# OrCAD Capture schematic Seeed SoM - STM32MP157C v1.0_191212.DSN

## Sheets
1 02 MPU_1: size A3; rev: v1.01
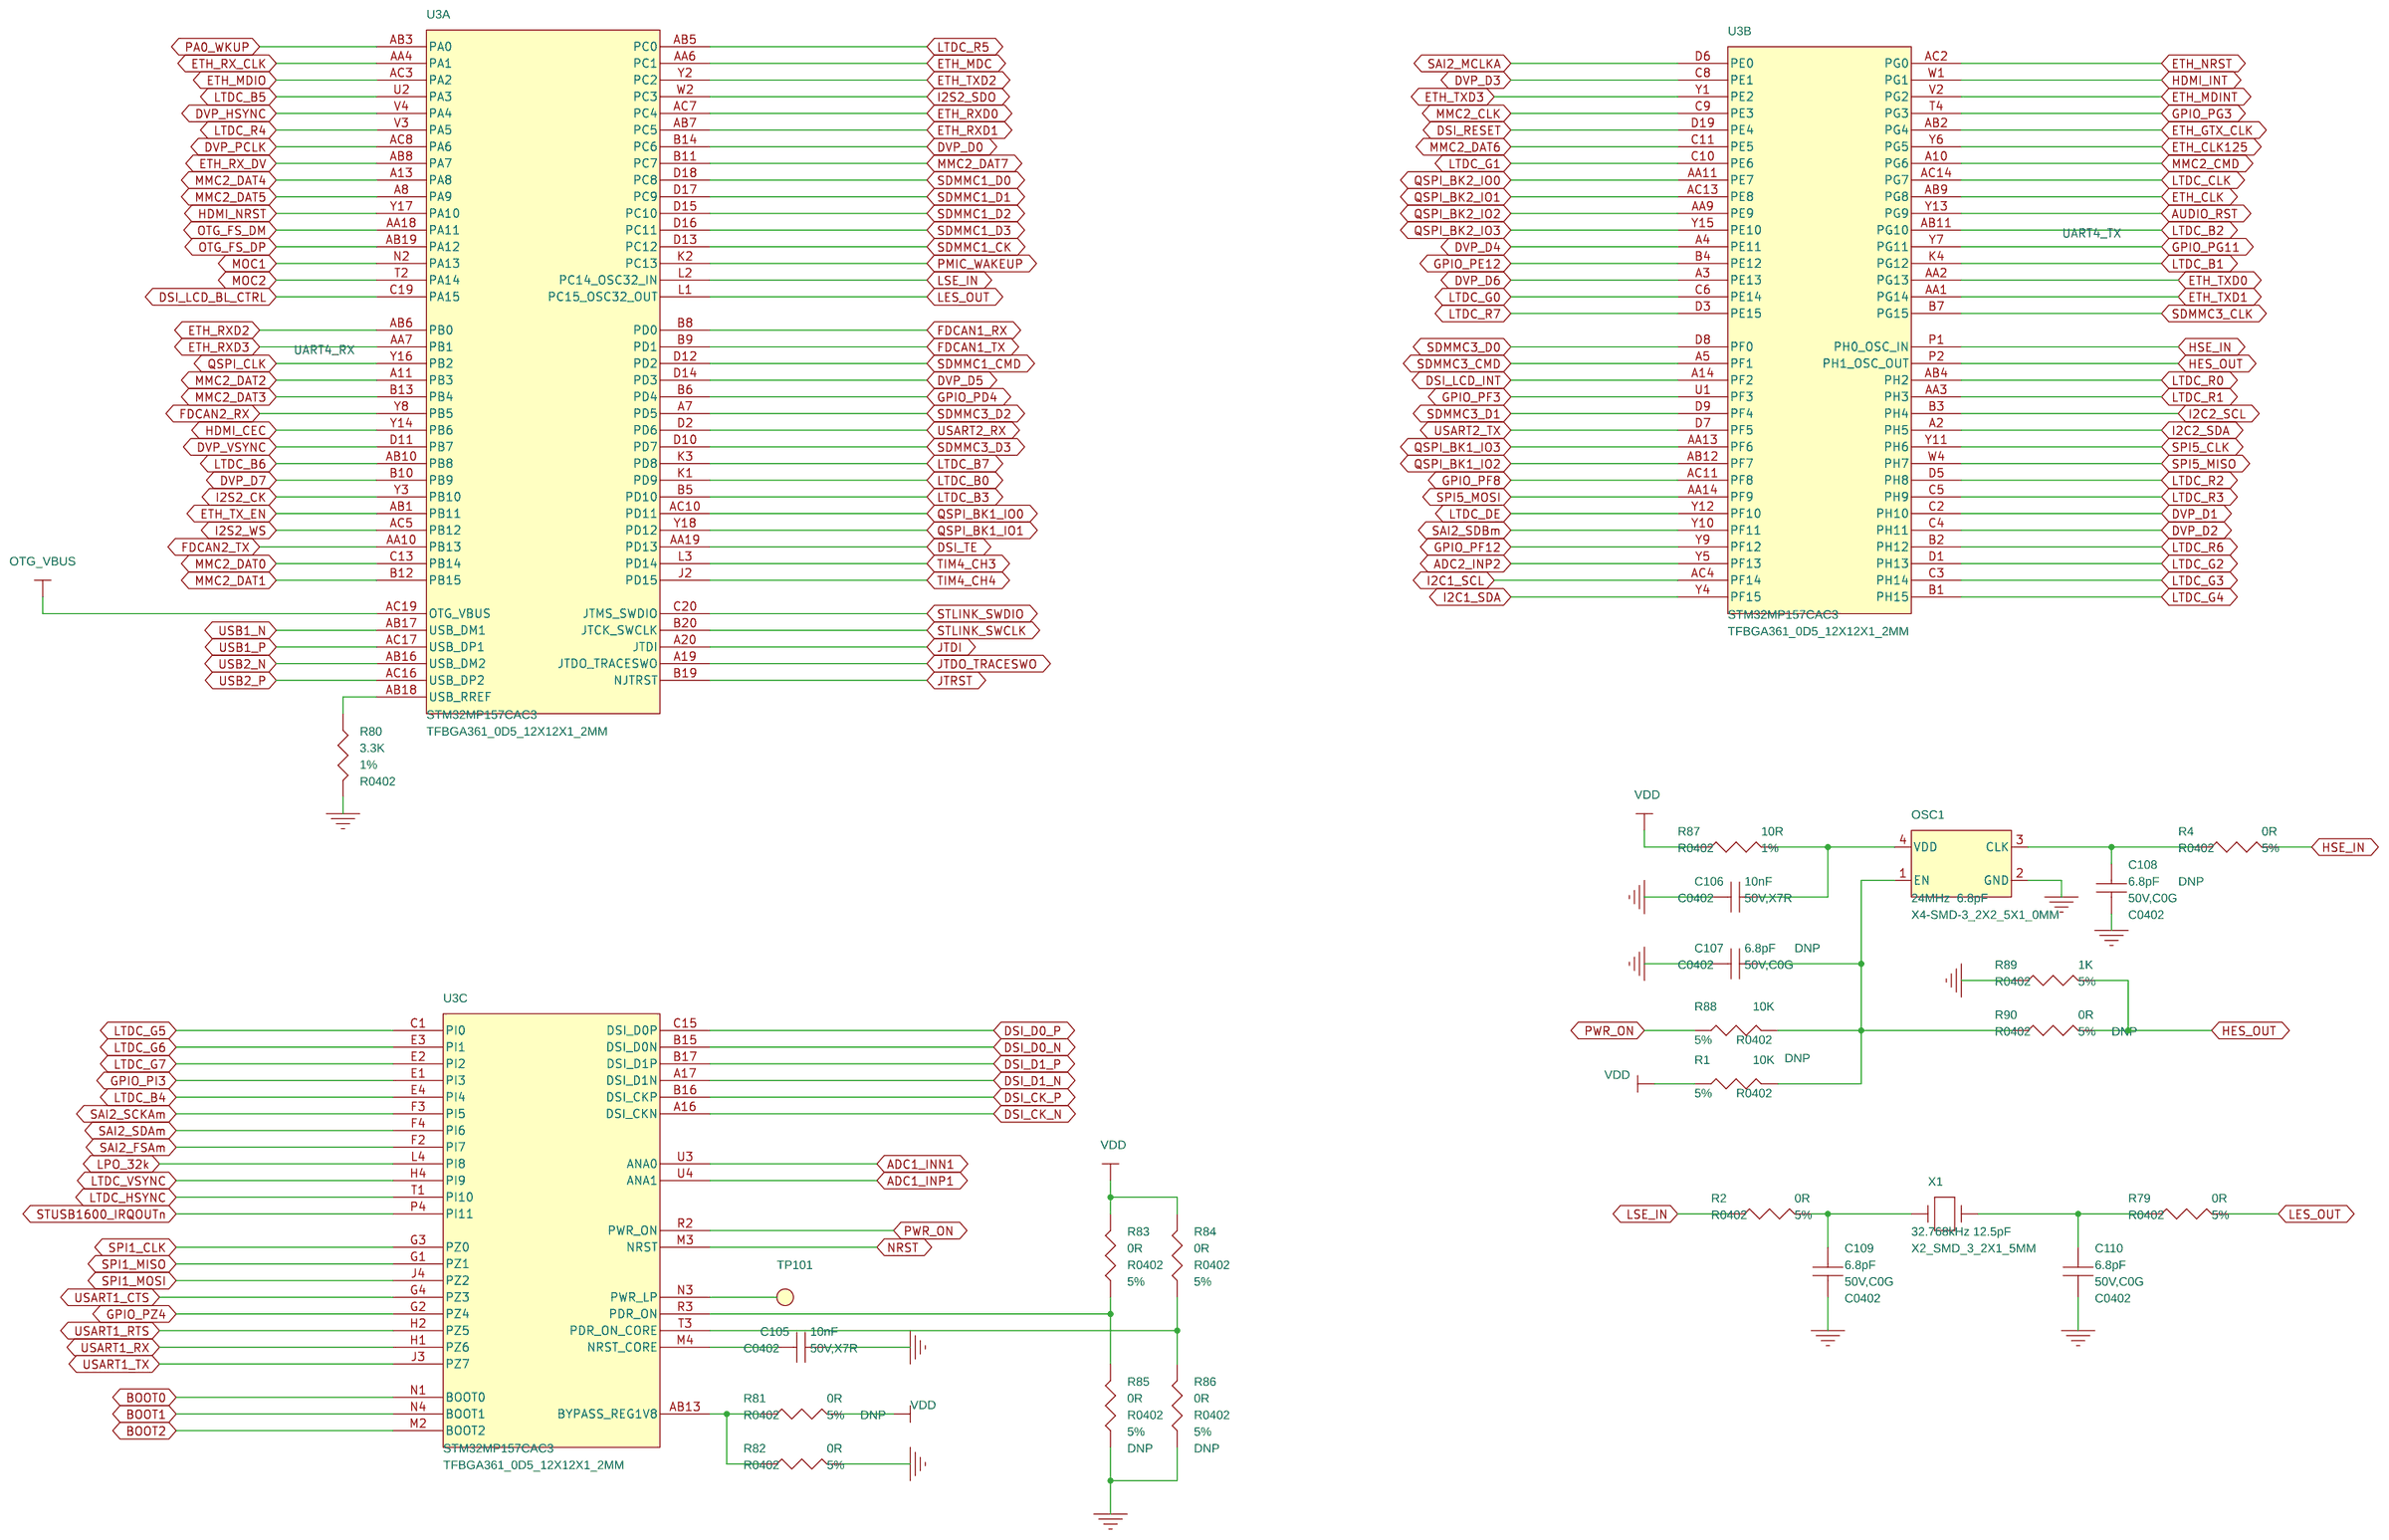
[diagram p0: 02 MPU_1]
2 03 MPU_2: size A3
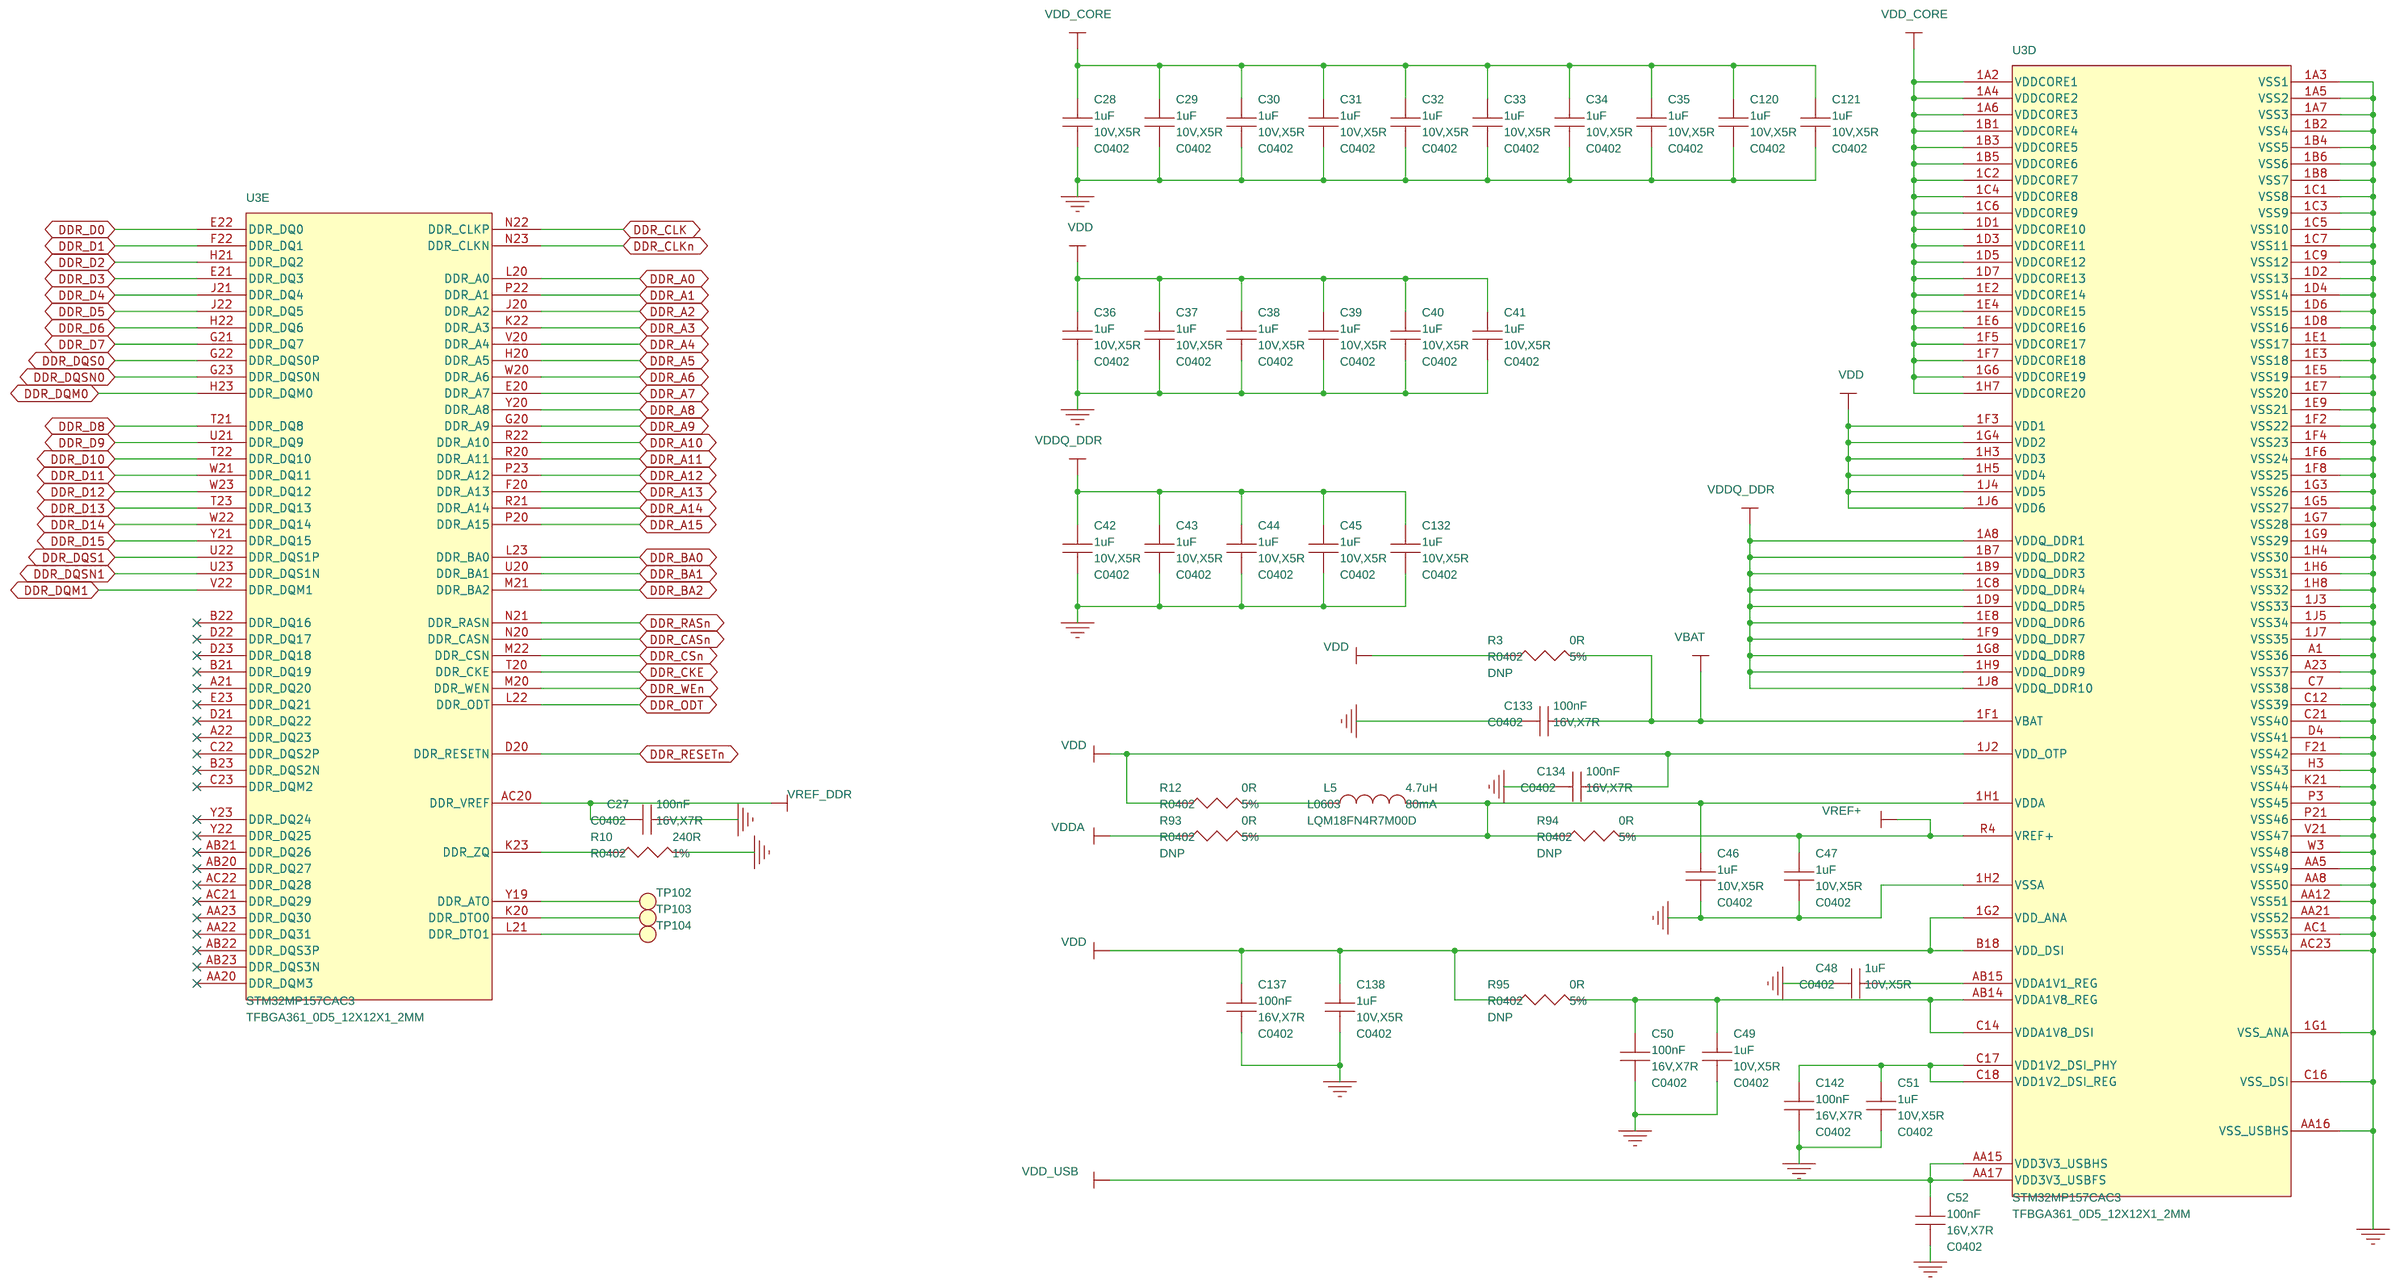
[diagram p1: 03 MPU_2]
3 04 DDR3: size A3
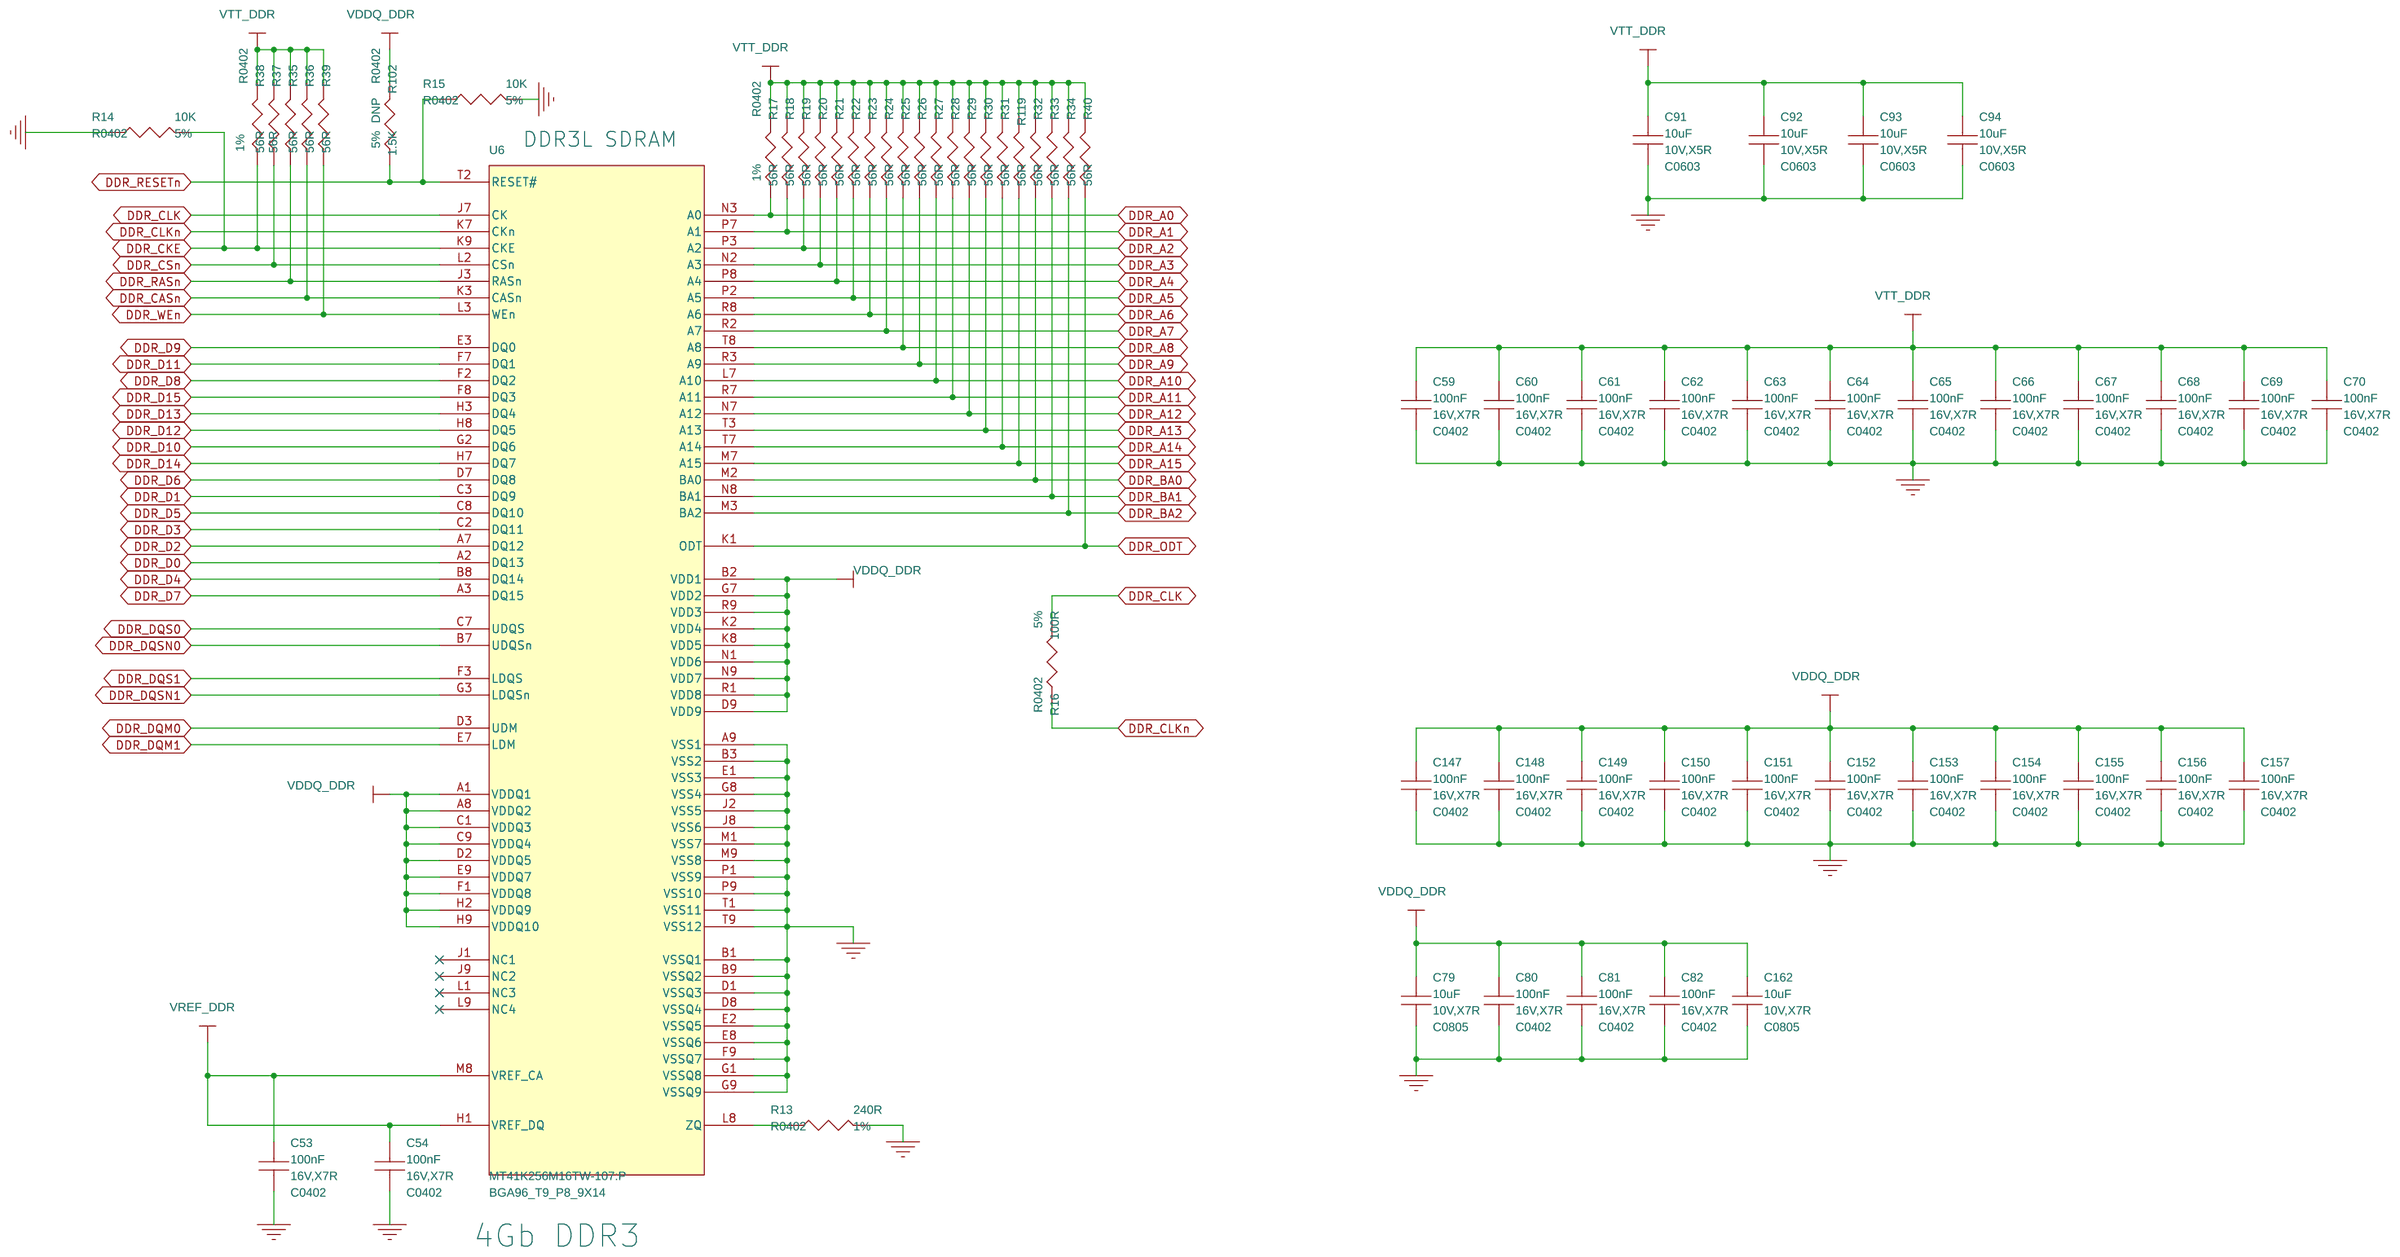
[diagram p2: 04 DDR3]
4 05 eMMC: size A3
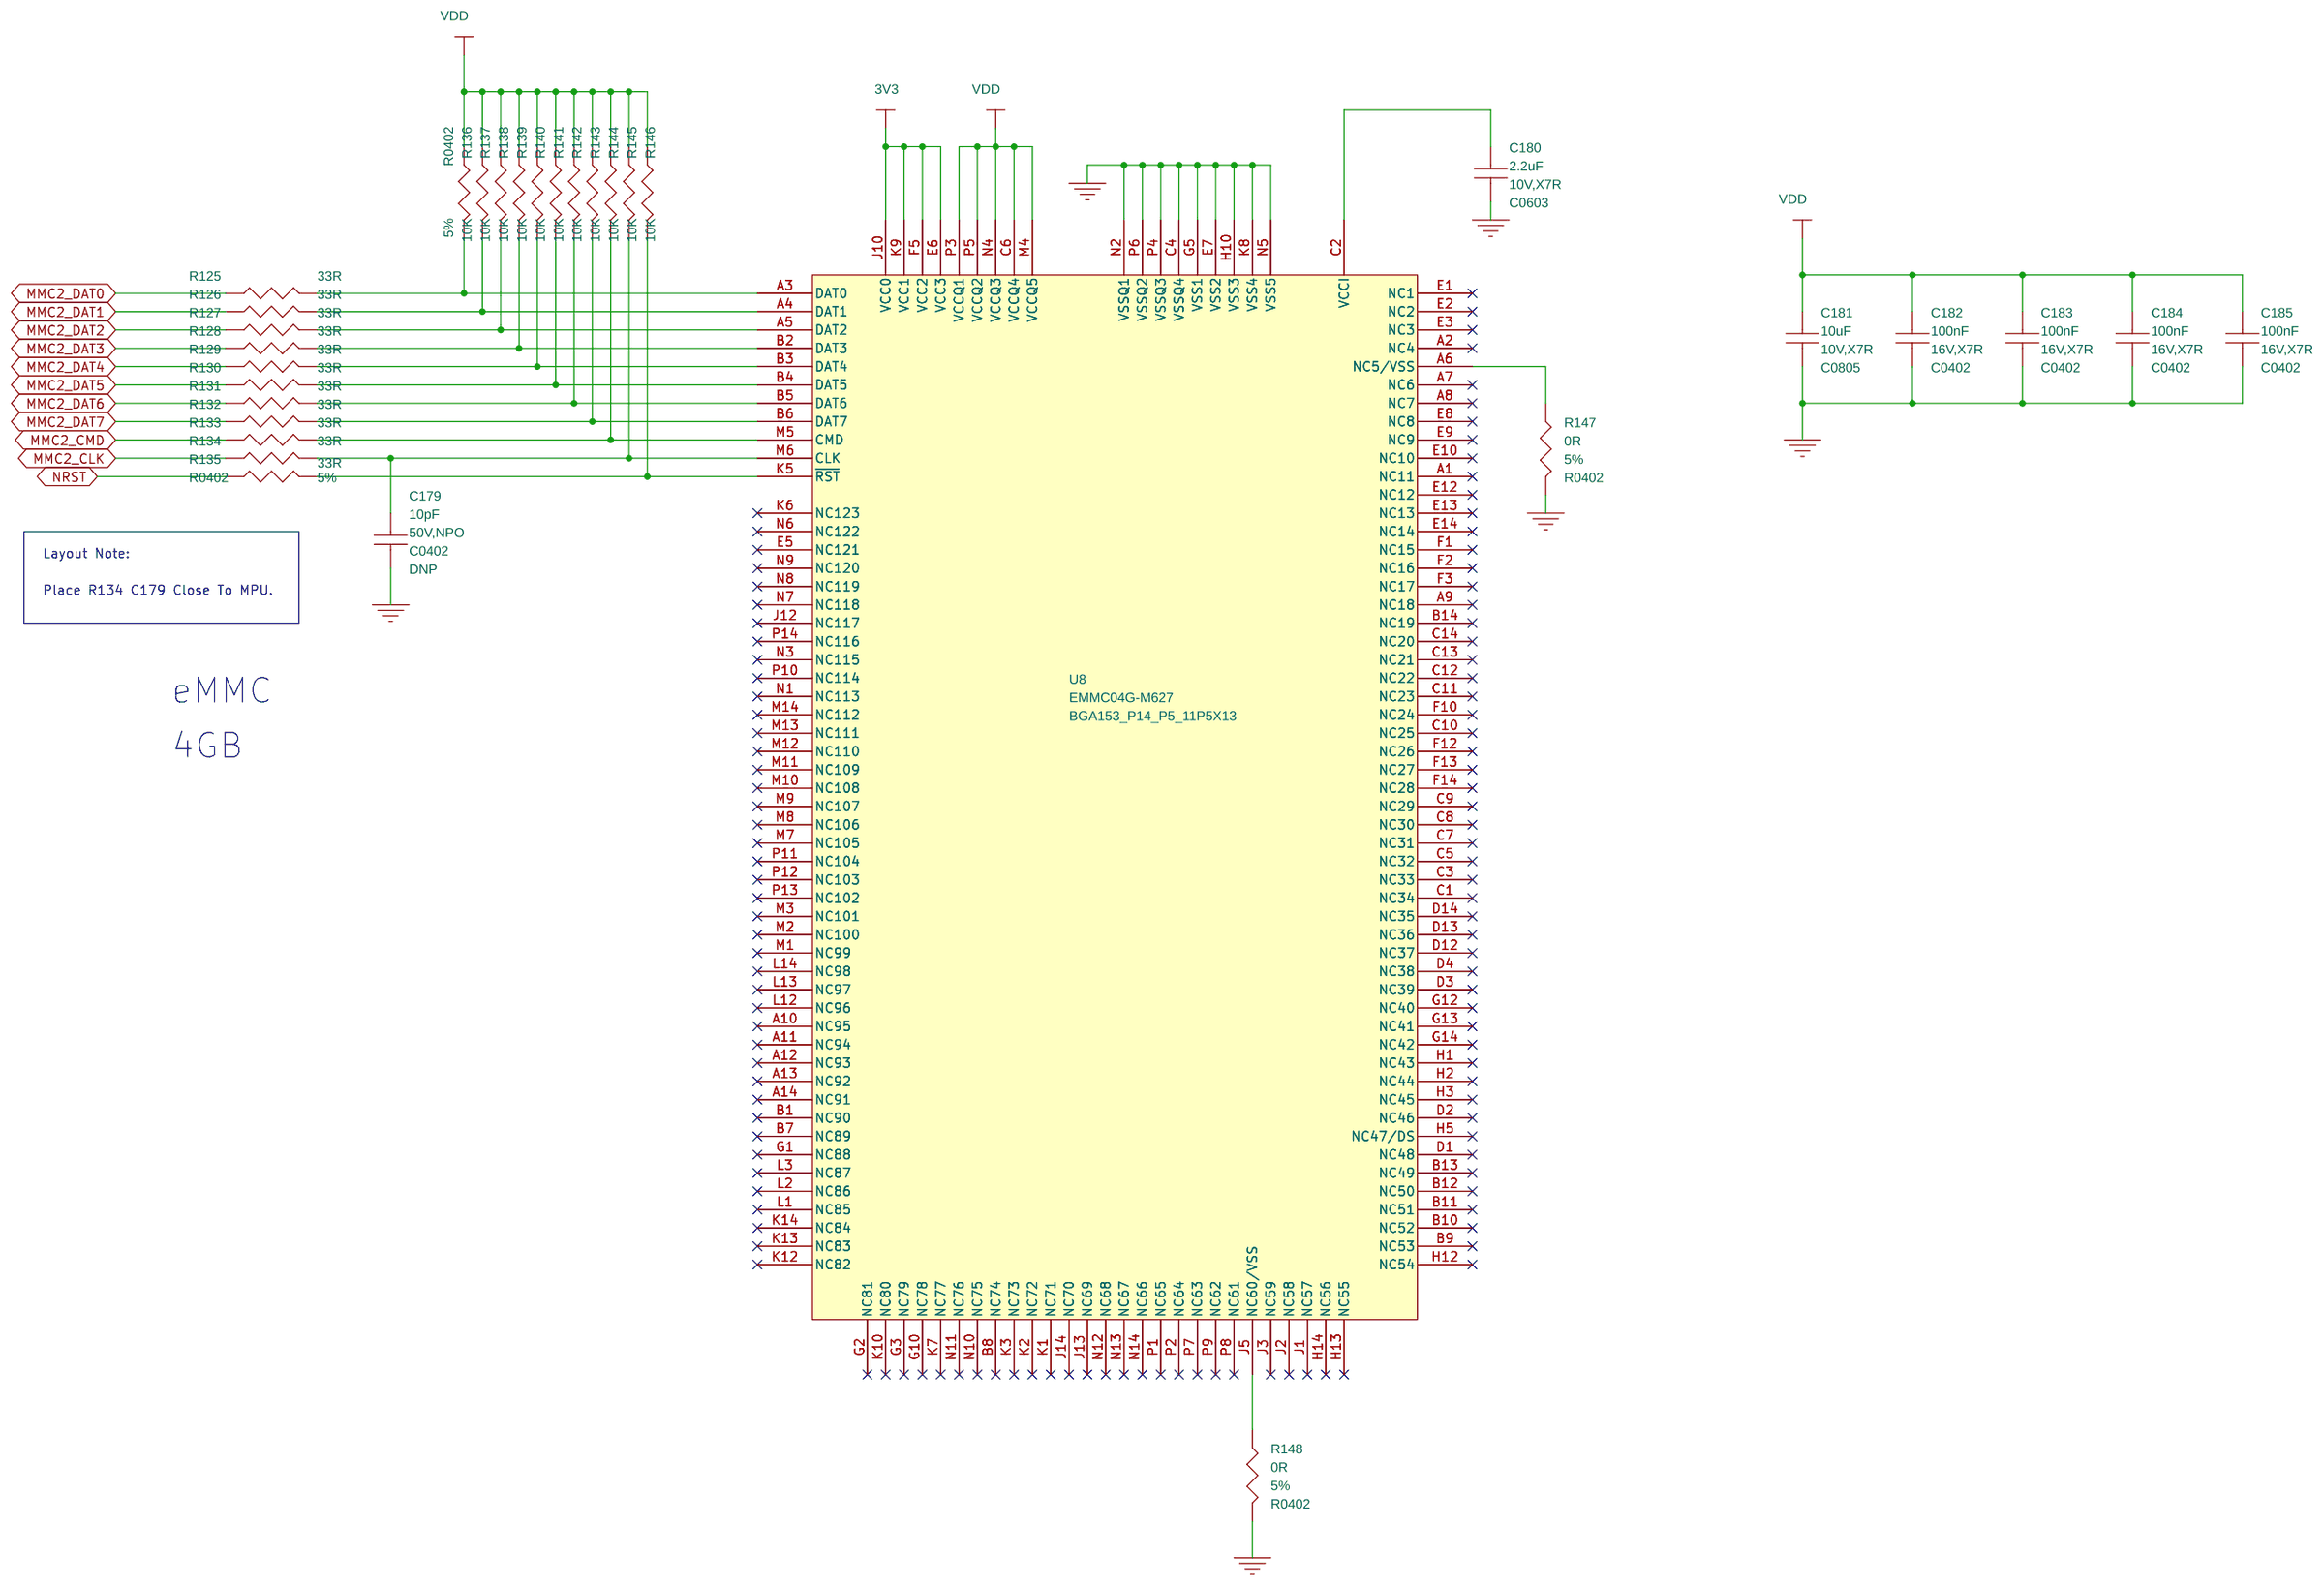
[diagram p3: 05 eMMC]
5 06 PMU: size A3
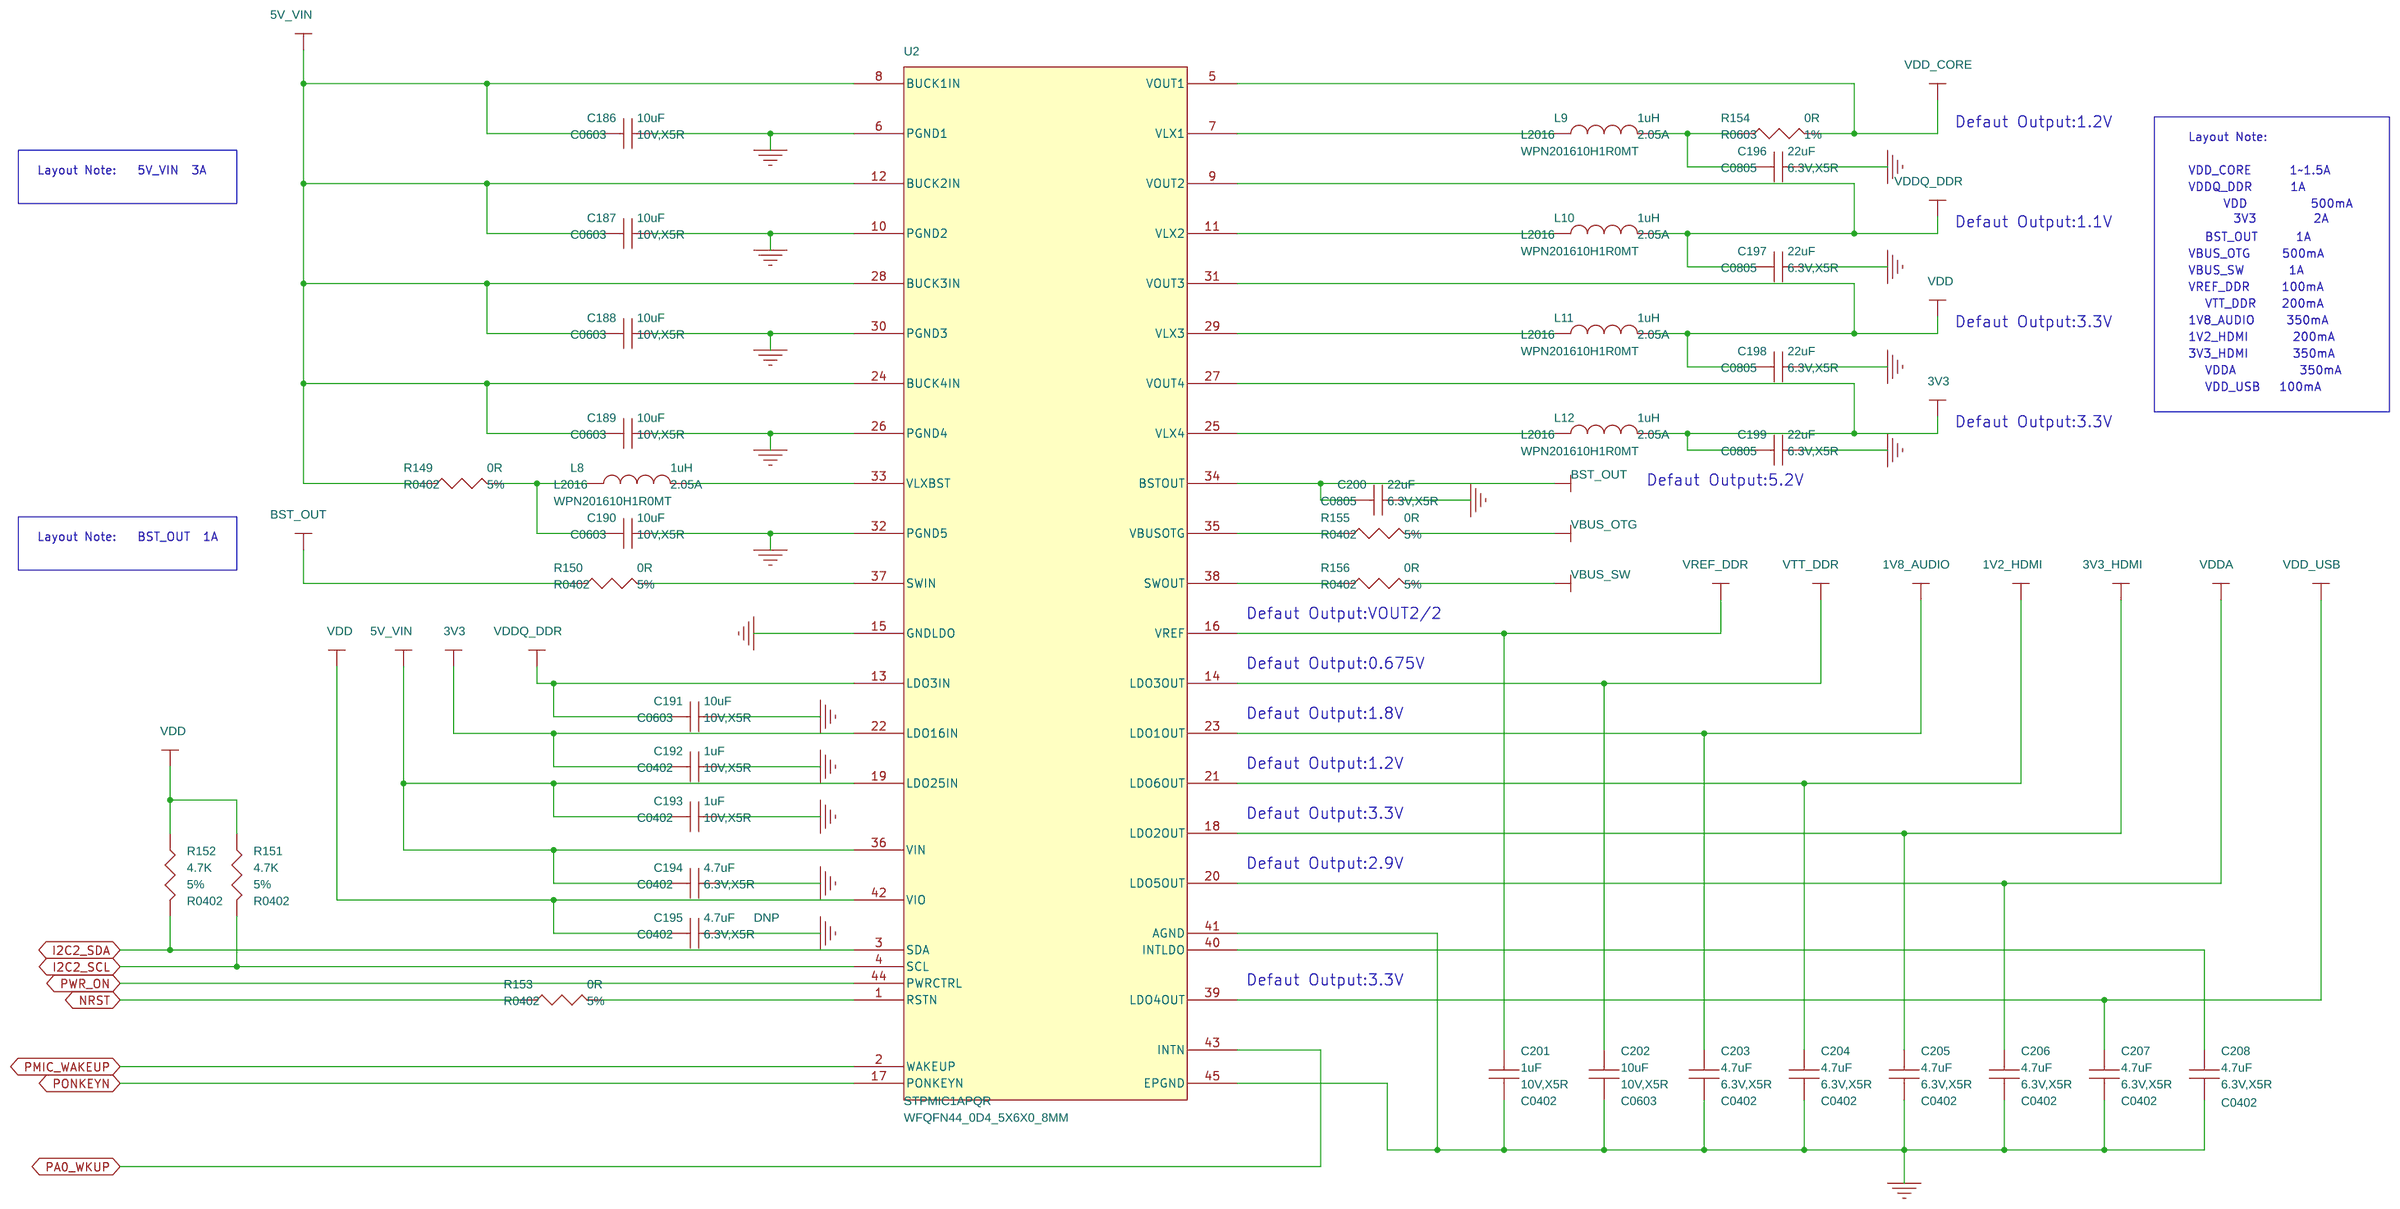
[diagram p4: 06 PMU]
6 07 PINOUT/LED: size A3
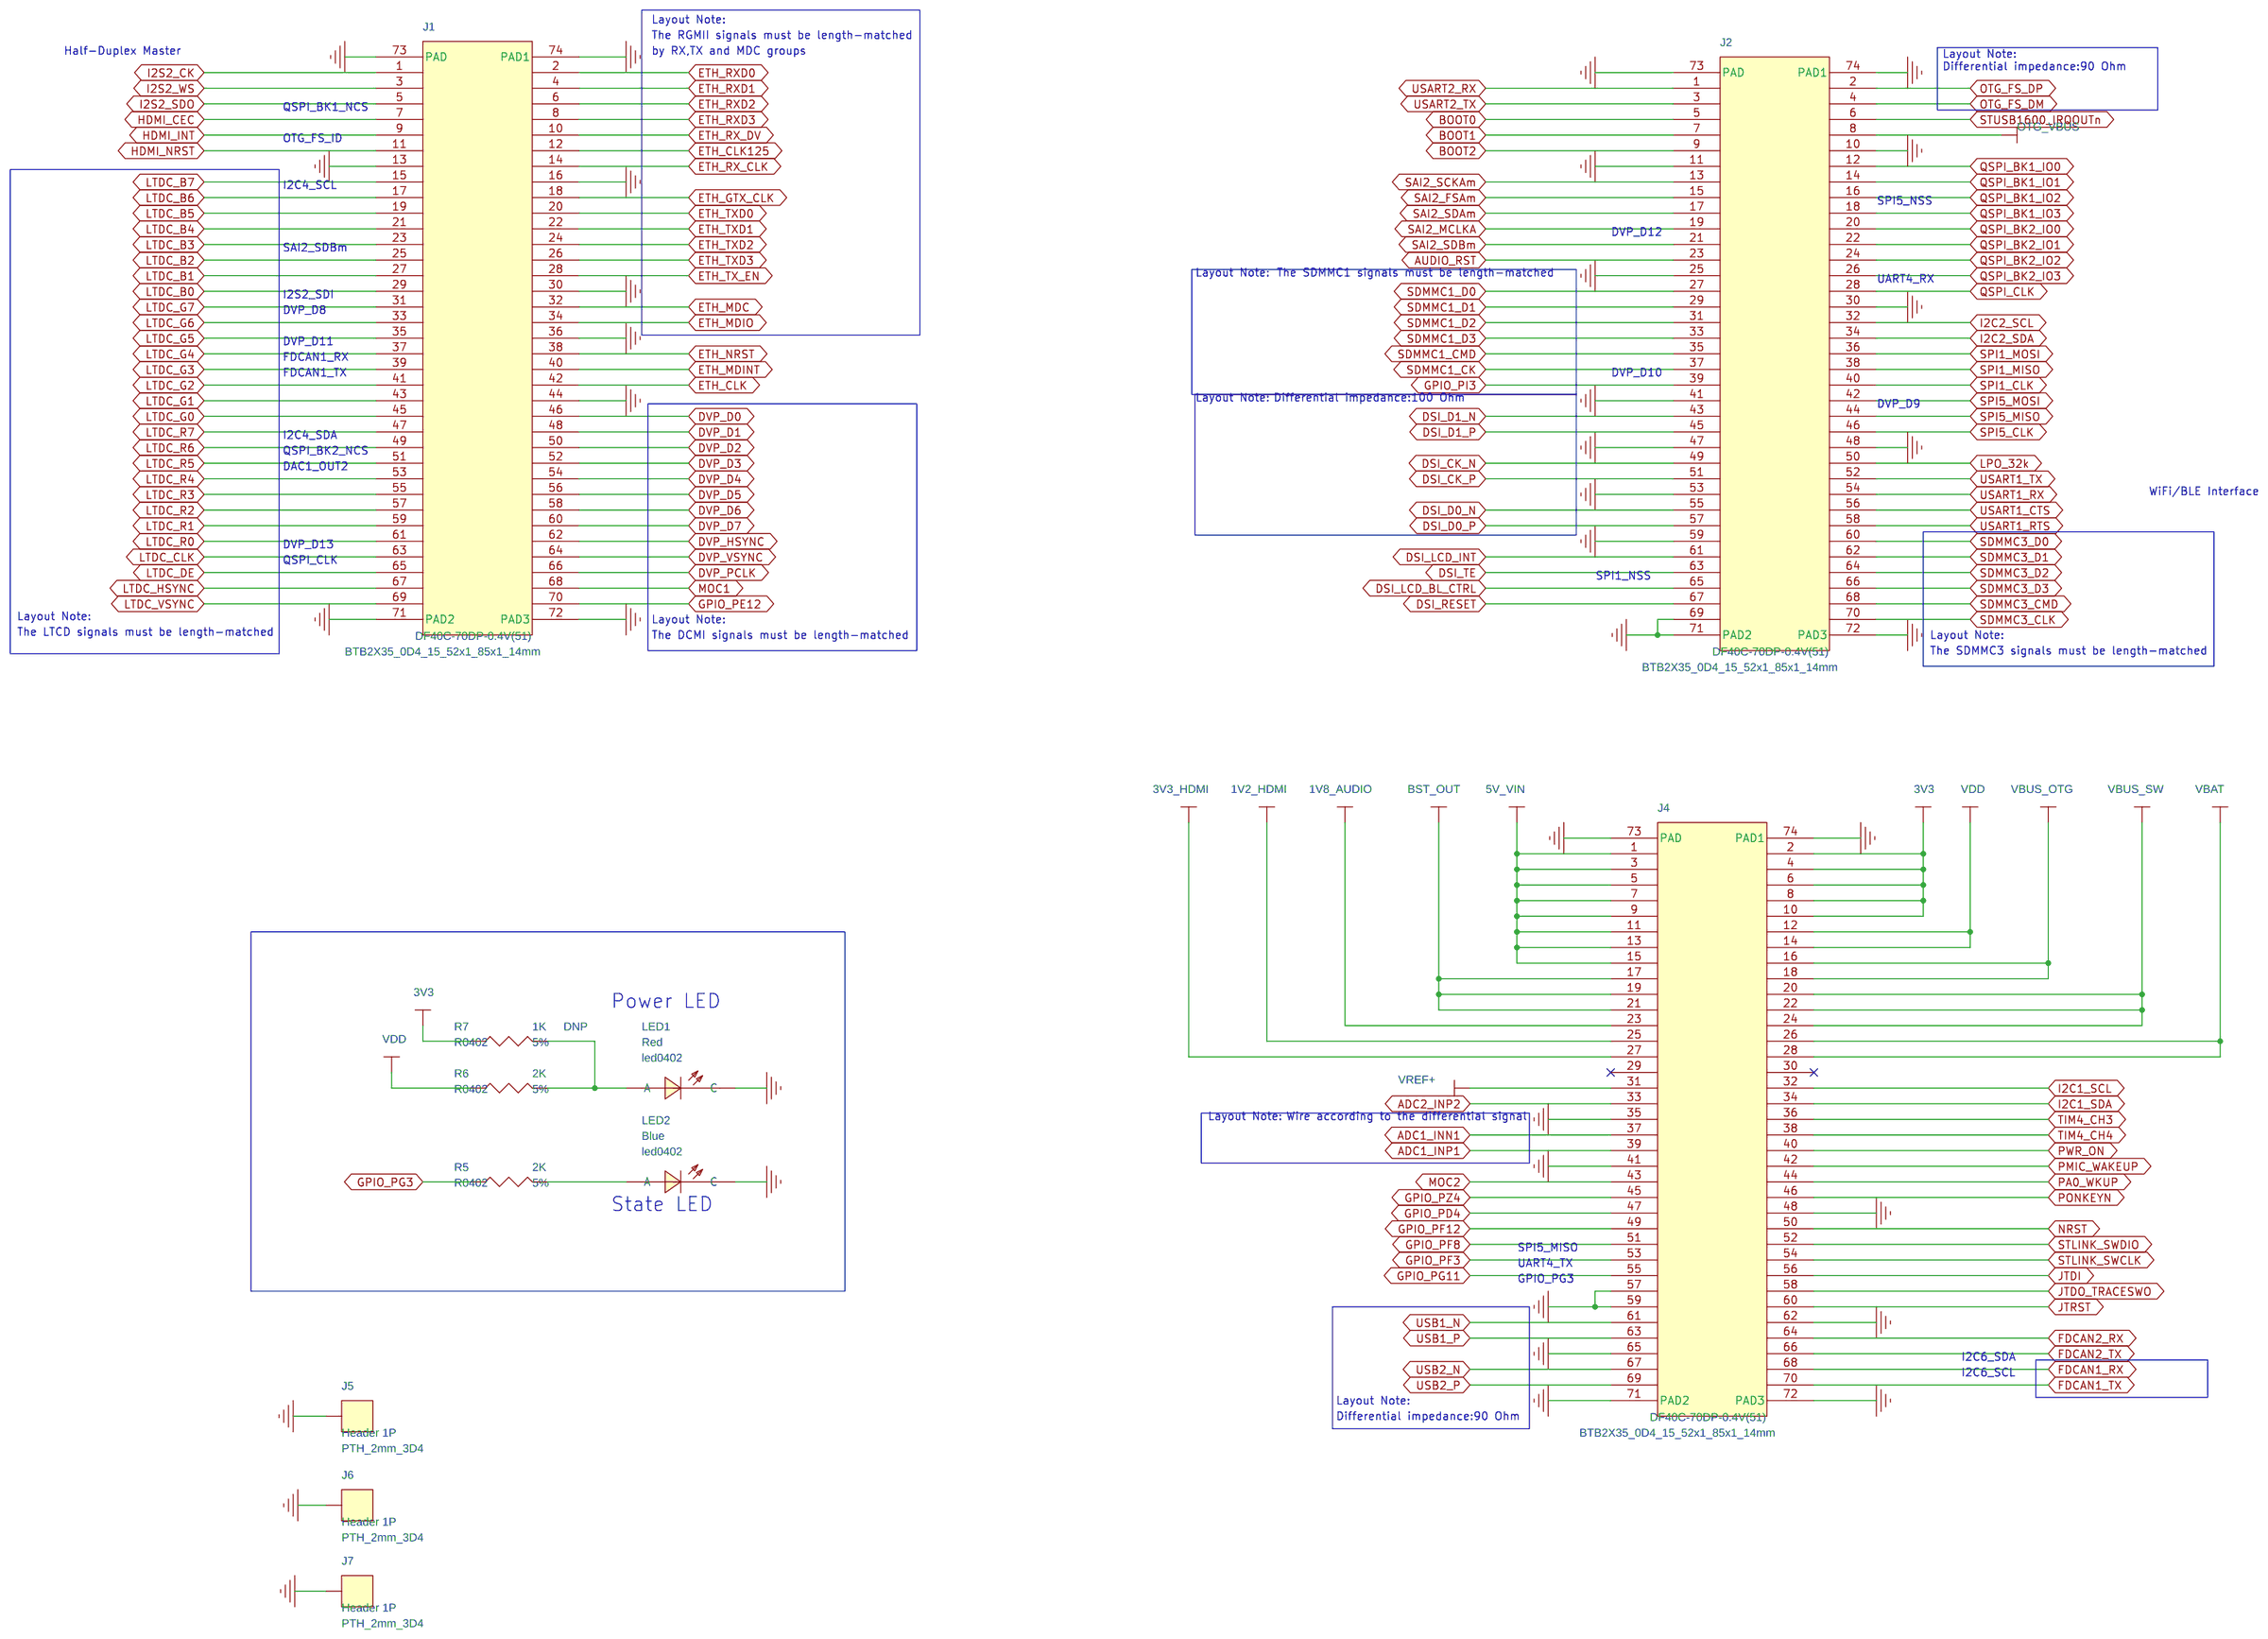
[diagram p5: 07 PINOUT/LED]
7 01 Title / Revision History
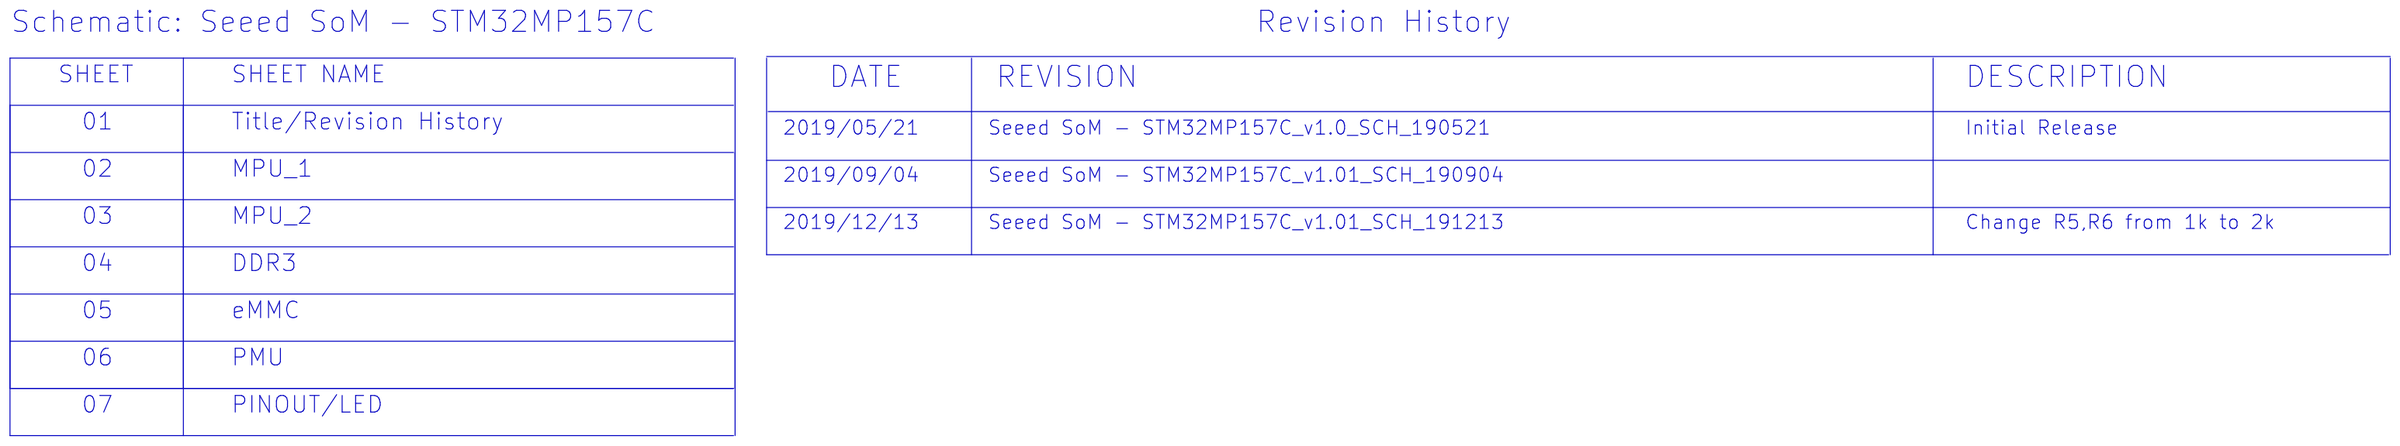
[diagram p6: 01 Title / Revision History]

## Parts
sheet 02 MPU_1
C105  10nF  [C0402]
C106  10nF  [C0402]
C107  6.8pF  [C0402]
C108  6.8pF  [C0402]
C109  6.8pF  [C0402]
C110  6.8pF  [C0402]
OSC1  24MHz  6.8pF  [X4-SMD-3_2X2_5X1_0MM]
R1  10K  [R0402]
R2  0R  [R0402]
R4  0R  [R0402]
R79  0R  [R0402]
R80  3.3K  [R0402]
R81  0R  [R0402]
R82  0R  [R0402]
R83  0R  [R0402]
R84  0R  [R0402]
R85  0R  [R0402]
R86  0R  [R0402]
R87  10R  [R0402]
R88  10K  [R0402]
R89  1K  [R0402]
R90  0R  [R0402]
TP101  Test TP35S_SMD  [TP35S_SMD]
U3  STM32MP157CAC3  [TFBGA361_0D5_12X12X1_2MM]  (sections A,B,C,D,E)
X1  32.768kHz 12.5pF  [X2_SMD_3_2X1_5MM]
sheet 03 MPU_2
C27  100nF  [C0402]
C28  1uF  [C0402]
C29  1uF  [C0402]
C30  1uF  [C0402]
C31  1uF  [C0402]
C32  1uF  [C0402]
C33  1uF  [C0402]
C34  1uF  [C0402]
C35  1uF  [C0402]
C36  1uF  [C0402]
C37  1uF  [C0402]
C38  1uF  [C0402]
C39  1uF  [C0402]
C40  1uF  [C0402]
C41  1uF  [C0402]
C42  1uF  [C0402]
C43  1uF  [C0402]
C44  1uF  [C0402]
C45  1uF  [C0402]
C46  1uF  [C0402]
C47  1uF  [C0402]
C48  1uF  [C0402]
C49  1uF  [C0402]
C50  100nF  [C0402]
C51  1uF  [C0402]
C52  100nF  [C0402]
C120  1uF  [C0402]
C121  1uF  [C0402]
C132  1uF  [C0402]
C133  100nF  [C0402]
C134  100nF  [C0402]
C137  100nF  [C0402]
C138  1uF  [C0402]
C142  100nF  [C0402]
L5  4.7uH  [L0603]
R3  0R  [R0402]
R10  240R  [R0402]
R12  0R  [R0402]
R93  0R  [R0402]
R94  0R  [R0402]
R95  0R  [R0402]
TP102  Test TP35S_SMD  [TP35S_SMD]
TP103  Test TP35S_SMD  [TP35S_SMD]
TP104  Test TP35S_SMD  [TP35S_SMD]
sheet 04 DDR3
C53  100nF  [C0402]
C54  100nF  [C0402]
C59  100nF  [C0402]
C60  100nF  [C0402]
C61  100nF  [C0402]
C62  100nF  [C0402]
C63  100nF  [C0402]
C64  100nF  [C0402]
C65  100nF  [C0402]
C66  100nF  [C0402]
C67  100nF  [C0402]
C68  100nF  [C0402]
C69  100nF  [C0402]
C70  100nF  [C0402]
C79  10uF  [C0805]
C80  100nF  [C0402]
C81  100nF  [C0402]
C82  100nF  [C0402]
C91  10uF  [C0603]
C92  10uF  [C0603]
C93  10uF  [C0603]
C94  10uF  [C0603]
C147  100nF  [C0402]
C148  100nF  [C0402]
C149  100nF  [C0402]
C150  100nF  [C0402]
C151  100nF  [C0402]
C152  100nF  [C0402]
C153  100nF  [C0402]
C154  100nF  [C0402]
C155  100nF  [C0402]
C156  100nF  [C0402]
C157  100nF  [C0402]
C162  10uF  [C0805]
R13  240R  [R0402]
R14  10K  [R0402]
R15  10K  [R0402]
R16  100R  [R0402]
R17  56R  [R0402]
R18  56R  [R0402]
R19  56R  [R0402]
R20  56R  [R0402]
R21  56R  [R0402]
R22  56R  [R0402]
R23  56R  [R0402]
R24  56R  [R0402]
R25  56R  [R0402]
R26  56R  [R0402]
R27  56R  [R0402]
R28  56R  [R0402]
R29  56R  [R0402]
R30  56R  [R0402]
R31  56R  [R0402]
R32  56R  [R0402]
R33  56R  [R0402]
R34  56R  [R0402]
R35  56R  [R0402]
R36  56R  [R0402]
R37  56R  [R0402]
R38  56R  [R0402]
R39  56R  [R0402]
R40  56R  [R0402]
R102  1.5K  [R0402]
R119  56R  [R0402]
U6  MT41K256M16TW-107:P  [BGA96_T9_P8_9X14]
sheet 05 eMMC
C179  10pF  [C0402]
C180  2.2uF  [C0603]
C181  10uF  [C0805]
C182  100nF  [C0402]
C183  100nF  [C0402]
C184  100nF  [C0402]
C185  100nF  [C0402]
R125  33R  [R0402]
R126  33R  [R0402]
R127  33R  [R0402]
R128  33R  [R0402]
R129  33R  [R0402]
R130  33R  [R0402]
R131  33R  [R0402]
R132  33R  [R0402]
R133  33R  [R0402]
R134  33R  [R0402]
R135  33R  [R0402]
R136  10K  [R0402]
R137  10K  [R0402]
R138  10K  [R0402]
R139  10K  [R0402]
R140  10K  [R0402]
R141  10K  [R0402]
R142  10K  [R0402]
R143  10K  [R0402]
R144  10K  [R0402]
R145  10K  [R0402]
R146  10K  [R0402]
R147  0R  [R0402]
R148  0R  [R0402]
U8  EMMC04G-M627  [BGA153_P14_P5_11P5X13]
sheet 06 PMU
C186  10uF  [C0603]
C187  10uF  [C0603]
C188  10uF  [C0603]
C189  10uF  [C0603]
C190  10uF  [C0603]
C191  10uF  [C0603]
C192  1uF  [C0402]
C193  1uF  [C0402]
C194  4.7uF  [C0402]
C195  4.7uF  [C0402]
C196  22uF  [C0805]
C197  22uF  [C0805]
C198  22uF  [C0805]
C199  22uF  [C0805]
C200  22uF  [C0805]
C201  1uF  [C0402]
C202  10uF  [C0603]
C203  4.7uF  [C0402]
C204  4.7uF  [C0402]
C205  4.7uF  [C0402]
C206  4.7uF  [C0402]
C207  4.7uF  [C0402]
C208  4.7uF  [C0402]
L8  1uH  [L2016]
L9  1uH  [L2016]
L10  1uH  [L2016]
L11  1uH  [L2016]
L12  1uH  [L2016]
R149  0R  [R0402]
R150  0R  [R0402]
R151  4.7K  [R0402]
R152  4.7K  [R0402]
R153  0R  [R0402]
R154  0R  [R0603]
R155  0R  [R0402]
R156  0R  [R0402]
U2  STPMIC1APQR  [WFQFN44_0D4_5X6X0_8MM]
sheet 07 PINOUT/LED
J1  DF40C-70DP-0.4V(51)  [BTB2X35_0D4_15_52x1_85x1_14mm]
J2  DF40C-70DP-0.4V(51)  [BTB2X35_0D4_15_52x1_85x1_14mm]
J4  DF40C-70DP-0.4V(51)  [BTB2X35_0D4_15_52x1_85x1_14mm]
J5  Header 1P  [PTH_2mm_3D4]
J6  Header 1P  [PTH_2mm_3D4]
J7  Header 1P  [PTH_2mm_3D4]
LED1  Red  [led0402]
LED2  Blue  [led0402]
R5  2K  [R0402]
R6  2K  [R0402]
R7  1K  [R0402]

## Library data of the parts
C105 C106 = CC: SMD CAP Ceramic 10nF-50V-10%-X7R;0402; Manufacturer: YAGEO; Manufacturer Part Number: CC0402KRX7R9BB103; PN: 302010006; Part Type: Ceramic; Rating: 50V,X7R; Status: BeagleBone Carrier Board; Temperature: -55°C to 125°C
C107 C108 = CC: SMD CAP Ceramic;6.8pF-50V-0.25pF-C0G-0402; ASSY: DNP; Manufacturer: Murata; Manufacturer Part Number: GRM1555C1H6R8CA01D; PN: 302010746; Part Type: Ceramic; Rating: 50V,C0G; Status: Seeed BeagleBone Green Gateway v1.1; Temperature: -55°C to 125°C
C109 C110 = CC: SMD CAP Ceramic;6.8pF-50V-0.25pF-C0G-0402; Manufacturer: Murata; Manufacturer Part Number: GRM1555C1H6R8CA01D; PN: 302010746; Part Type: Ceramic; Rating: 50V,C0G; Status: Seeed BeagleBone Green Gateway v1.1; Temperature: -55°C to 125°C
OSC1 = OSC_4P: SMD Oscillator;24MHz-50ppm-4P-3.2*2.5mm; Manufacturer: EPSON; Manufacturer Part Number: SG-310SCF 24.0000MB3; PN: 306020541; Part Type: Oscillator; Rating: 50ppm; Status: ST; Temperature: -20°C to 70°C
R1 = R: SMD RES 10K-5%-1/16W;0402; ASSY: DNP; Manufacturer: YAGEO; Manufacturer Part Number: RC0402JR-0710KL; PN: 301010004; Part Type: RES; Rating: 5%; Status: BeagleBone Carrier Board; Temperature: -55°C to 155°C
R2 R4 R12 R79 R82-R84 R147-R150 R153 R155 R156 = R: SMD RES 0R-5%-1/16W;0402; Manufacturer: YAGEO; Manufacturer Part Number: RC0402JR-070RL; PN: 301010000; Part Type: RES; Rating: 5%; Status: BeagleBone Carrier Board; Temperature: -55°C to 155°C
R80 = R: SMD RES 3.3K-5%-1/16W;0402; Manufacturer: YAGEO; Manufacturer Part Number: RC0402JR-073K3L; PN: 301010035; Part Type: RES; Rating: 1%; Status: Not Used; Temperature: -55°C to 155°C
R3 R81 R85 R86 R90 R93-R95 = R: SMD RES 0R-5%-1/16W;0402; ASSY: DNP; Manufacturer: YAGEO; Manufacturer Part Number: RC0402JR-070RL; PN: 301010000; Part Type: RES; Rating: 5%; Status: BeagleBone Carrier Board; Temperature: -55°C to 155°C
R87 = R: SMD RES 10R-1%-1/16W;0402; Manufacturer: YAGEO; Manufacturer Part Number: RC0402FR-0710RL; PN: 301010444; Part Type: RES; Rating: 1%; Status: IOT Enabling Dongle Board; Temperature: -55°C to 155°C
R14 R15 R88 R136-R146 = R: SMD RES 10K-5%-1/16W;0402; Manufacturer: YAGEO; Manufacturer Part Number: RC0402JR-0710KL; PN: 301010004; Part Type: RES; Rating: 5%; Status: BeagleBone Carrier Board; Temperature: -55°C to 155°C
R89 = R: SMD RES 1K-5%-1/16W;0402; Manufacturer: YAGEO; Manufacturer Part Number: RC0402JR-071KL; PN: 301010006; Part Type: RES; Rating: 5%; Status: BeagleBone Carrier Board; Temperature: -55°C to 155°C
TP101-TP104 = TEST_POINT: Test Point;TP35S_SMD; Part Type: Test Point; Status: Combox Pro
U3 = STM32MP157CAC3: SMD IC MPU;TFBGA361; Manufacturer: ST; PN: 310011097; Part Type: MCU; Status: ST; Temperature: -40°C to 125°C
X1 = XTAL_2P: SMD Crystal 32.768KHz-12.5pF-20ppm-2P-3.2*1.5*0.9mm; Manufacturer: EPCOS; Manufacturer Part Number: FC-135 32.7680KA-A3; PN: 306010138; Part Type: Crystal; Rating: 20ppm; Status: BeagleBone Carrier Board
C27 C50 C52-C54 C59-C70 C80-C82 C133 C134 C137 C142 C147-C157 C182-C185 = CC: SMD CAP Ceramic 100nF-16V-10%-X7R;0402; Manufacturer: Murata; Manufacturer Part Number: GRM155R71C104KA88D; PN: 302011380; Part Type: Ceramic; Rating: 16V,X7R; Status: Combox Pro; Temperature: -55°C to 125°C
C28-C49 C51 C120 C121 C132 C138 C192 C193 C201 = CC: SMD CAP Ceramic 1uF-10V-10%-X5R;0402; Manufacturer: YAGEO; Manufacturer Part Number: CC0402KRX5R6BB105; PN: 302010040; Part Type: Ceramic; Rating: 10V,X5R; Status: BeagleBone Carrier Board; Temperature: -55°C to 85°C
L5 = L: SMD Inductor 4.7uH-20%-80mA;0603; Manufacturer: Murata; Manufacturer Part Number: LQM18FN4R7M00D; PN: 303011269; Part Type: Inductor; Rating: 80mA; Status: ST; Temperature: -55°C to 125°C
R10 R13 = R: SMD RES 240R-1%-1/16W;0402; Manufacturer: YAGEO; Manufacturer Part Number: RC0402FR-07240RL; PN: 301011475; Part Type: RES; Rating: 1%; Status: Combox Pro; Temperature: -55°C to 155°C
C79 C162 C181 = CC: SMD CAP Ceramic 10uF-10V-10%-X7R;0805; Manufacturer: Murata; Manufacturer Part Number: GRM21BR71A106KA73L; PN: 302011379; Part Type: Ceramic; Rating: 10V,X7R; Status: Combox Pro; Temperature: -55°C to 125°C
C91-C94 C186-C191 C202 = CC: SMD CAP Ceramic 10uF-10V-10%-X5R;0603; Manufacturer: YAGEO; Manufacturer Part Number: CC0603KRX5R6BB106; PN: 302010103; Part Type: Ceramic; Rating: 10V,X5R; Status: BeagleBone Carrier Board; Temperature: -55°C to 85°C
R16 = R: SMD RES 100R-5%-1/16W;0402; Manufacturer: YAGEO; Manufacturer Part Number: RC0402JR-07100RL; PN: 301010028; Part Type: RES; Rating: 5%; Status: BeagleBone Carrier Board; Temperature: -55°C to 155°C
R17-R40 R119 = R: SMD RES 56R-1%-1/16W;0402; Manufacturer: YAGEO; Manufacturer Part Number: RC0402FR-0756RL; PN: 301012337; Part Type: RES; Rating: 1%; Status: ST; Temperature: -55°C to 155°C
R102 = R: SMD RES 1.5K-5%-1/16W;0402; ASSY: DNP; Manufacturer: YAGEO; Manufacturer Part Number: RC0402JR-071K5L; PN: 301010001; Part Type: RES; Rating: 5%; Status: BeagleBone Carrier Board; Temperature: -55°C to 155°C
U6 = DDR3_96-ball_FBGA: SMD IC Memory;TFBGA-96（8x14); Manufacturer: Micron; PN: 310090304; Part Type: DDR; Status: ST; Temperature: 0°C to 95°C
C179 = CC: SMD CAP Ceramic 10pF-50V-2%-NPO;0402; ASSY: DNP; Manufacturer: Murata; Manufacturer Part Number: GRM1555C1H100GA01D; PN: 302010047; Part Type: Ceramic; Rating: 50V,NPO; Status: Combox Pro; Temperature: -55°C to 125°C
C180 = CC: SMD CAP Ceramic 2.2uF-10V-10%-X7R;0603; Manufacturer: Murata; Manufacturer Part Number: GRM188R71A225KE15D; PN: 302011383; Part Type: Ceramic; Rating: 10V,X7R; Status: Combox Pro; Temperature: -55°C to 125°C
R125-R135 = R: SMD RES 33R-5%-1/16W;0402; Manufacturer: YAGEO; Manufacturer Part Number: RC0402JR-0733RL; PN: 301010034; Part Type: RES; Rating: 5%; Status: BeagleBone Carrier Board; Temperature: -55°C to 155°C
U8 = eMMC_153-ball_WFBGA: SMD IC Memory;VFBGA-153; Manufacturer: Kingston; PN: 310090564; Part Type: eMMC; Status: BeagleBone Carrier Board; Temperature: -25°C to 85°C
C194 C203-C208 = CC: SMD CAP Ceramic 4.7uF-6.3V-20%-X5R;0402; Manufacturer: YAGEO; Manufacturer Part Number: CC0402MRX5R5BB475; PN: 302010019; Part Type: Ceramic; Rating: 6.3V,X5R; Status: BeagleBone Carrier Board; Temperature: -55°C to 85°C
C195 = CC: SMD CAP Ceramic 4.7uF-6.3V-20%-X5R;0402; ASSY: DNP; Manufacturer: YAGEO; Manufacturer Part Number: CC0402MRX5R5BB475; PN: 302010019; Part Type: Ceramic; Rating: 6.3V,X5R; Status: BeagleBone Carrier Board; Temperature: -55°C to 85°C
C196-C200 = CC: SMD CAP Ceramic 22uF-6.3V-20%-X5R;0805; Manufacturer: YAGEO; Manufacturer Part Number: CC0805MKX5R5BB226; PN: 302010171; Part Type: Ceramic; Rating: 6.3V,X5R; Status: RT-M7; Temperature: -55°C to 85°C
L8-L12 = L: SMD Inductor 1uH-20%;L2.0*W1.6*H1.0mm; Manufacturer: Sunlord; Manufacturer Part Number: WPN201610H1R0MT; PN: 303010925; Part Type: Inductor; Rating: 2.05A; Status: Sensecap Gateway V1; Temperature: -40°C to 125°C
R151 R152 = R: SMD RES 4.7K-5%-1/16W;0402; Manufacturer: YAGEO; Manufacturer Part Number: RC0402JR-074K7L; PN: 301010010; Part Type: RES; Rating: 5%; Status: BeagleBone Carrier Board; Temperature: -55°C to 155°C
R154 = R: SMD RES 0R-1%-1/10W;0603; Manufacturer: YAGEO; Manufacturer Part Number: RC0603JR-070RL; PN: 301010203; Part Type: RES; Rating: 1%; Status: BeagleBone Carrier Board; Temperature: -55°C to 155°C
U2 = STPMIC1APQR: SMD IC PMIC;WFQFN 44L; Manufacturer: ST; PN: 310031749; Part Type: PMIC; Status: ST; Temperature: -40°C to 85°C
J1 J2 J4 = Header_2X35+4p: SMD BTB CONN Header;70P-0.4-L15.52*W2.97*H1.14mm; Manufacturer: HRS; PN: 320210007; Part Type: BTB Connector; Status: ST
J5-J7 = Header_1P: Part Type: Locating hole; Rating: 2MM_PTH定位孔; Status: ST
LED1 = Single_LED: SMD LED Clear-Red;0402; Manufacturer: Bright; Manufacturer Part Number: BL-HUB37A-AV-TRB; PN: 304090122; Part Type: LED; Status: ST; Temperature: -40°C to 85°C
LED2 = Single_LED: SMD LED Clear-Blue;0402; Manufacturer: Bright; Manufacturer Part Number: BL-HB337A-AV-TRB; PN: 304090075; Part Type: LED; Status: ST; Temperature: -40°C to 85°C
R5 R6 = R: SMD RES 2K-5%-1/16W;0402; Manufacturer: YAGEO; Manufacturer Part Number: RC0402JR-072KL; PN: 301010065; Part Type: RES; Rating: 5%; Status: Grove AI HAT for Edge Computing; Temperature: -55°C to 155°C
R7 = R: SMD RES 1K-5%-1/16W;0402; ASSY: DNP; Manufacturer: YAGEO; Manufacturer Part Number: RC0402JR-071KL; PN: 301010006; Part Type: RES; Rating: 5%; Status: BeagleBone Carrier Board; Temperature: -55°C to 155°C

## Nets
1V2_HDMI: C204.1 J4.25 U2.21(LDO6OUT)
1V8_AUDIO: C203.1 J4.23 U2.23(LDO1OUT)
3V3: C192.1 C199.1 J4.2 J4.4 J4.6 J4.8 J4.10 L12.2 R7.1 U2.22(LDO16IN) U2.27(VOUT4) U8.E6(VCC3) U8.F5(VCC2) U8.J10(VCC0) U8.K9(VCC1)
3V3_HDMI: C205.1 J4.27 U2.18(LDO2OUT)
5V_VIN: C186.1 C187.1 C188.1 C189.1 C193.1 C194.1 J4.1 J4.3 J4.5 J4.7 J4.9 J4.11 J4.13 J4.15 R149.1 U2.8(BUCK1IN) U2.12(BUCK2IN) U2.19(LDO25IN) U2.24(BUCK4IN) U2.28(BUCK3IN) U2.36(VIN)
GND: C27.2 C28.2 C29.2 C30.2 C31.2 C32.2 C33.2 C34.2 C35.2 C36.2 C37.2 C38.2 C39.2 C40.2 C41.2 C42.2 C43.2 C44.2 C45.2 C46.2 C47.2 C48.1 C49.2 C50.2 C51.2 C52.2 C53.2 C54.2 C59.2 C60.2 C61.2 C62.2 C63.2 C64.2 C65.2 C66.2 C67.2 C68.2 C69.2 C70.2 C79.2 C80.2 C81.2 C82.2 C91.2 C92.2 C93.2 C94.2 C105.2 C106.1 C107.1 C108.2 C109.2 C110.2 C120.2 C121.2 C132.2 C133.1 C134.1 C137.2 C138.2 C142.2 C147.2 C148.2 C149.2 C150.2 C151.2 C152.2 C153.2 C154.2 C155.2 C156.2 C157.2 C162.2 C179.2 C180.2 C181.2 C182.2 C183.2 C184.2 C185.2 C186.2 C187.2 C188.2 C189.2 C190.2 C191.2 C192.2 C193.2 C194.2 C195.2 C196.2 C197.2 C198.2 C199.2 C200.2 C201.2 C202.2 C203.2 C204.2 C205.2 C206.2 C207.2 C208.2 J1.13 J1.16 J1.30 J1.36 J1.44 J1.71(PAD2) J1.72(PAD3) J1.73(PAD) J1.74(PAD1) J2.10 J2.11 J2.25 J2.30 J2.41 J2.47 J2.48 J2.53 J2.59 J2.69 J2.71(PAD2) J2.72(PAD3) J2.73(PAD) J2.74(PAD1) J4.35 J4.41 J4.48 J4.57 J4.59 J4.62 J4.65 J4.71(PAD2) J4.72(PAD3) J4.73(PAD) J4.74(PAD1) J5.1 J6.1 J7.1 LED1.2(C) LED2.2(C) OSC1.2(GND) R10.2 R13.2 R14.1 R15.2 R80.2 R82.2 R85.1 R86.1 R89.1 R147.2 R148.2 U2.6(PGND1) U2.10(PGND2) U2.15(GNDLDO) U2.26(PGND4) U2.30(PGND3) U2.32(PGND5) U2.41(AGND) U2.45(EPGND) U3.1A3(VSS1) U3.1A5(VSS2) U3.1A7(VSS3) U3.1B2(VSS4) U3.1B4(VSS5) U3.1B6(VSS6) U3.1B8(VSS7) U3.1C1(VSS8) U3.1C3(VSS9) U3.1C5(VSS10) U3.1C7(VSS11) U3.1C9(VSS12) U3.1D2(VSS13) U3.1D4(VSS14) U3.1D6(VSS15) U3.1D8(VSS16) U3.1E1(VSS17) U3.1E3(VSS18) U3.1E5(VSS19) U3.1E7(VSS20) U3.1E9(VSS21) U3.1F2(VSS22) U3.1F4(VSS23) U3.1F6(VSS24) U3.1F8(VSS25) U3.1G1(VSS_ANA) U3.1G3(VSS26) U3.1G5(VSS27) U3.1G7(VSS28) U3.1G9(VSS29) U3.1H2(VSSA) U3.1H4(VSS30) U3.1H6(VSS31) U3.1H8(VSS32) U3.1J3(VSS33) U3.1J5(VSS34) U3.1J7(VSS35) U3.A1(VSS36) U3.A23(VSS37) U3.AA5(VSS49) U3.AA8(VSS50) U3.AA12(VSS51) U3.AA16(VSS_USBHS) U3.AA21(VSS52) U3.AC1(VSS53) U3.AC23(VSS54) U3.C7(VSS38) U3.C12(VSS39) U3.C16(VSS_DSI) U3.C21(VSS40) U3.D4(VSS41) U3.F21(VSS42) U3.H3(VSS43) U3.K21(VSS44) U3.P3(VSS45) U3.P21(VSS46) U3.V21(VSS47) U3.W3(VSS48) U6.A9(VSS1) U6.B1(VSSQ1) U6.B3(VSS2) U6.B9(VSSQ2) U6.D1(VSSQ3) U6.D8(VSSQ4) U6.E1(VSS3) U6.E2(VSSQ5) U6.E8(VSSQ6) U6.F9(VSSQ7) U6.G1(VSSQ8) U6.G8(VSS4) U6.G9(VSSQ9) U6.J2(VSS5) U6.J8(VSS6) U6.M1(VSS7) U6.M9(VSS8) U6.P1(VSS9) U6.P9(VSS10) U6.T1(VSS11) U6.T9(VSS12) U8.C4(VSSQ4) U8.E7(VSS2) U8.G5(VSS1) U8.H10(VSS3) U8.K8(VSS4) U8.N2(VSSQ1) U8.N5(VSS5) U8.P4(VSSQ3) U8.P6(VSSQ2)
VBAT: C133.2 J4.26 J4.28 R3.2 U3.1F1(VBAT)
VBUS_OTG: J4.16 J4.18 R155.2
VBUS_SW: J4.20 J4.22 J4.24 R156.2
VDD: C36.1 C37.1 C38.1 C39.1 C40.1 C41.1 C134.2 C137.1 C138.1 C181.1 C182.1 C183.1 C184.1 C185.1 C195.1 C198.1 J4.12 J4.14 L11.2 R1.1 R3.1 R6.1 R12.1 R81.2 R83.2 R84.2 R87.1 R95.1 R136.1 R137.1 R138.1 R139.1 R140.1 R141.1 R142.1 R143.1 R144.1 R145.1 R146.1 R151.1 R152.1 U2.31(VOUT3) U2.42(VIO) U3.1F3(VDD1) U3.1G2(VDD_ANA) U3.1G4(VDD2) U3.1H3(VDD3) U3.1H5(VDD4) U3.1J2(VDD_OTP) U3.1J4(VDD5) U3.1J6(VDD6) U3.B18(VDD_DSI) U8.C6(VCCQ4) U8.M4(VCCQ5) U8.N4(VCCQ3) U8.P3(VCCQ1) U8.P5(VCCQ2)
VDD_CORE: C28.1 C29.1 C30.1 C31.1 C32.1 C33.1 C34.1 C35.1 C120.1 C121.1 R154.2 U2.5(VOUT1) U3.1A2(VDDCORE1) U3.1A4(VDDCORE2) U3.1A6(VDDCORE3) U3.1B1(VDDCORE4) U3.1B3(VDDCORE5) U3.1B5(VDDCORE6) U3.1C2(VDDCORE7) U3.1C4(VDDCORE8) U3.1C6(VDDCORE9) U3.1D1(VDDCORE10) U3.1D3(VDDCORE11) U3.1D5(VDDCORE12) U3.1D7(VDDCORE13) U3.1E2(VDDCORE14) U3.1E4(VDDCORE15) U3.1E6(VDDCORE16) U3.1F5(VDDCORE17) U3.1F7(VDDCORE18) U3.1G6(VDDCORE19) U3.1H7(VDDCORE20)
VDD_USB: C52.1 C207.1 U2.39(LDO4OUT) U3.AA15(VDD3V3_USBHS) U3.AA17(VDD3V3_USBFS)
VDDA: C206.1 R93.1 U2.20(LDO5OUT)
VDDQ_DDR: C42.1 C43.1 C44.1 C45.1 C79.1 C80.1 C81.1 C82.1 C132.1 C147.1 C148.1 C149.1 C150.1 C151.1 C152.1 C153.1 C154.1 C155.1 C156.1 C157.1 C162.1 C191.1 C197.1 L10.2 R102.2 U2.9(VOUT2) U2.13(LDO3IN) U3.1A8(VDDQ_DDR1) U3.1B7(VDDQ_DDR2) U3.1B9(VDDQ_DDR3) U3.1C8(VDDQ_DDR4) U3.1D9(VDDQ_DDR5) U3.1E8(VDDQ_DDR6) U3.1F9(VDDQ_DDR7) U3.1G8(VDDQ_DDR8) U3.1H9(VDDQ_DDR9) U3.1J8(VDDQ_DDR10) U6.A1(VDDQ1) U6.A8(VDDQ2) U6.B2(VDD1) U6.C1(VDDQ3) U6.C9(VDDQ4) U6.D2(VDDQ5) U6.D9(VDD9) U6.E9(VDDQ7) U6.F1(VDDQ8) U6.G7(VDD2) U6.H2(VDDQ9) U6.H9(VDDQ10) U6.K2(VDD4) U6.K8(VDD5) U6.N1(VDD6) U6.N9(VDD7) U6.R1(VDD8) U6.R9(VDD3)
ADC1_INN1: J4.37 U3.U3(ANA0)
ADC1_INP1: J4.39 U3.U4(ANA1)
ADC2_INP2: J4.33 U3.Y5(PF13)
AUDIO_RST: J2.23 U3.Y13(PG9)
BOOT0: J2.5 U3.N1(BOOT0)
BOOT1: J2.7 U3.N4(BOOT1)
BOOT2: J2.9 U3.M2(BOOT2)
BST_OUT: C200.1 J4.17 J4.19 J4.21 R150.1 U2.34(BSTOUT)
DDR_A0: R17.1 U3.L20(DDR_A0) U6.N3(A0)
DDR_A1: R18.1 U3.P22(DDR_A1) U6.P7(A1)
DDR_A2: R19.1 U3.J20(DDR_A2) U6.P3(A2)
DDR_A3: R20.1 U3.K22(DDR_A3) U6.N2(A3)
DDR_A4: R21.1 U3.V20(DDR_A4) U6.P8(A4)
DDR_A5: R22.1 U3.H20(DDR_A5) U6.P2(A5)
DDR_A6: R23.1 U3.W20(DDR_A6) U6.R8(A6)
DDR_A7: R24.1 U3.E20(DDR_A7) U6.R2(A7)
DDR_A8: R25.1 U3.Y20(DDR_A8) U6.T8(A8)
DDR_A9: R26.1 U3.G20(DDR_A9) U6.R3(A9)
DDR_A10: R27.1 U3.R22(DDR_A10) U6.L7(A10)
DDR_A11: R28.1 U3.R20(DDR_A11) U6.R7(A11)
DDR_A12: R29.1 U3.P23(DDR_A12) U6.N7(A12)
DDR_A13: R30.1 U3.F20(DDR_A13) U6.T3(A13)
DDR_A14: R31.1 U3.R21(DDR_A14) U6.T7(A14)
DDR_A15: R119.1 U3.P20(DDR_A15) U6.M7(A15)
DDR_BA0: R32.1 U3.L23(DDR_BA0) U6.M2(BA0)
DDR_BA1: R33.1 U3.U20(DDR_BA1) U6.N8(BA1)
DDR_BA2: R34.1 U3.M21(DDR_BA2) U6.M3(BA2)
DDR_CASn: R36.1 U3.N20(DDR_CASN) U6.K3(CASn)
DDR_CKE: R14.2 R38.1 U3.T20(DDR_CKE) U6.K9(CKE)
DDR_CLK: R16.2 U3.N22(DDR_CLKP) U6.J7(CK)
DDR_CLKn: R16.1 U3.N23(DDR_CLKN) U6.K7(CKn)
DDR_CSn: R37.1 U3.M22(DDR_CSN) U6.L2(CSn)
DDR_D0: U3.E22(DDR_DQ0) U6.A2(DQ13)
DDR_D1: U3.F22(DDR_DQ1) U6.C3(DQ9)
DDR_D2: U3.H21(DDR_DQ2) U6.A7(DQ12)
DDR_D3: U3.E21(DDR_DQ3) U6.C2(DQ11)
DDR_D4: U3.J21(DDR_DQ4) U6.B8(DQ14)
DDR_D5: U3.J22(DDR_DQ5) U6.C8(DQ10)
DDR_D6: U3.H22(DDR_DQ6) U6.D7(DQ8)
DDR_D7: U3.G21(DDR_DQ7) U6.A3(DQ15)
DDR_D8: U3.T21(DDR_DQ8) U6.F2(DQ2)
DDR_D9: U3.U21(DDR_DQ9) U6.E3(DQ0)
DDR_D10: U3.T22(DDR_DQ10) U6.G2(DQ6)
DDR_D11: U3.W21(DDR_DQ11) U6.F7(DQ1)
DDR_D12: U3.W23(DDR_DQ12) U6.H8(DQ5)
DDR_D13: U3.T23(DDR_DQ13) U6.H3(DQ4)
DDR_D14: U3.W22(DDR_DQ14) U6.H7(DQ7)
DDR_D15: U3.Y21(DDR_DQ15) U6.F8(DQ3)
DDR_DQM0: U3.H23(DDR_DQM0) U6.D3(UDM)
DDR_DQM1: U3.V22(DDR_DQM1) U6.E7(LDM)
DDR_DQS0: U3.G22(DDR_DQS0P) U6.C7(UDQS)
DDR_DQS1: U3.U22(DDR_DQS1P) U6.F3(LDQS)
DDR_DQSN0: U3.G23(DDR_DQS0N) U6.B7(UDQSn)
DDR_DQSN1: U3.U23(DDR_DQS1N) U6.G3(LDQSn)
DDR_ODT: R40.1 U3.L22(DDR_ODT) U6.K1(ODT)
DDR_RASn: R35.1 U3.N21(DDR_RASN) U6.J3(RASn)
DDR_RESETn: R15.1 R102.1 U3.D20(DDR_RESETN) U6.T2(RESET#)
DDR_WEn: R39.1 U3.M20(DDR_WEN) U6.L3(WEn)
DSI_CK_N: J2.49 U3.A16(DSI_CKN)
DSI_CK_P: J2.51 U3.B16(DSI_CKP)
DSI_D0_N: J2.55 U3.B15(DSI_D0N)
DSI_D0_P: J2.57 U3.C15(DSI_D0P)
DSI_D1_N: J2.43 U3.A17(DSI_D1N)
DSI_D1_P: J2.45 U3.B17(DSI_D1P)
DSI_LCD_BL_CTRL: J2.65 U3.C19(PA15)
DSI_LCD_INT: J2.61 U3.A14(PF2)
DSI_RESET: J2.67 U3.D19(PE4)
DSI_TE: J2.63 U3.AA19(PD13)
DVP_D0: J1.46 U3.B14(PC6)
DVP_D1: J1.48 U3.C2(PH10)
DVP_D2: J1.50 U3.C4(PH11)
DVP_D3: J1.52 U3.C8(PE1)
DVP_D4: J1.54 U3.A4(PE11)
DVP_D5: J1.56 U3.D14(PD3)
DVP_D6: J1.58 U3.A3(PE13)
DVP_D7: J1.60 U3.B10(PB9)
DVP_HSYNC: J1.62 U3.V4(PA4)
DVP_PCLK: J1.66 U3.AC8(PA6)
DVP_VSYNC: J1.64 U3.D11(PB7)
ETH_CLK: J1.42 U3.AB9(PG8)
ETH_CLK125: J1.12 U3.Y6(PG5)
ETH_GTX_CLK: J1.18 U3.AB2(PG4)
ETH_MDC: J1.32 U3.AA6(PC1)
ETH_MDINT: J1.40 U3.V2(PG2)
ETH_MDIO: J1.34 U3.AC3(PA2)
ETH_NRST: J1.38 U3.AC2(PG0)
ETH_RX_CLK: J1.14 U3.AA4(PA1)
ETH_RX_DV: J1.10 U3.AB8(PA7)
ETH_RXD0: J1.2 U3.AC7(PC4)
ETH_RXD1: J1.4 U3.AB7(PC5)
ETH_RXD2: J1.6 U3.AB6(PB0)
ETH_RXD3: J1.8 U3.AA7(PB1)
ETH_TX_EN: J1.28 U3.AB1(PB11)
ETH_TXD0: J1.20 U3.AA2(PG13)
ETH_TXD1: J1.22 U3.AA1(PG14)
ETH_TXD2: J1.24 U3.Y2(PC2)
ETH_TXD3: J1.26 U3.Y1(PE2)
FDCAN1_RX: J4.68 U3.B8(PD0)
FDCAN1_TX: J4.70 U3.B9(PD1)
FDCAN2_RX: J4.64 U3.Y8(PB5)
FDCAN2_TX: J4.66 U3.AA10(PB13)
GPIO_PD4: J4.47 U3.B6(PD4)
GPIO_PE12: J1.70 U3.B4(PE12)
GPIO_PF3: J4.53 U3.U1(PF3)
GPIO_PF8: J4.51 U3.AC11(PF8)
GPIO_PF12: J4.49 U3.Y9(PF12)
GPIO_PG3: R5.1 U3.T4(PG3)
GPIO_PG11: J4.55 U3.Y7(PG11)
GPIO_PI3: J2.39 U3.E1(PI3)
GPIO_PZ4: J4.45 U3.G2(PZ4)
HDMI_CEC: J1.7 U3.Y14(PB6)
HDMI_INT: J1.9 U3.W1(PG1)
HDMI_NRST: J1.11 U3.Y17(PA10)
HES_OUT: R89.2 R90.2 U3.P2(PH1_OSC_OUT)
HSE_IN: R4.2 U3.P1(PH0_OSC_IN)
I2C1_SCL: J4.32 U3.AC4(PF14)
I2C1_SDA: J4.34 U3.Y4(PF15)
I2C2_SCL: J2.32 R151.2 U2.4(SCL) U3.B3(PH4)
I2C2_SDA: J2.34 R152.2 U2.3(SDA) U3.A2(PH5)
I2S2_CK: J1.1 U3.Y3(PB10)
I2S2_SDO: J1.5 U3.W2(PC3)
I2S2_WS: J1.3 U3.AC5(PB12)
JTDI: J4.56 U3.A20(JTDI)
JTDO_TRACESWO: J4.58 U3.A19(JTDO_TRACESWO)
JTRST: J4.60 U3.B19(NJTRST)
LES_OUT: R79.2 U3.L1(PC15_OSC32_OUT)
LPO_32k: J2.50 U3.L4(PI8)
LSE_IN: R2.1 U3.L2(PC14_OSC32_IN)
LTDC_B0: J1.29 U3.K1(PD9)
LTDC_B1: J1.27 U3.K4(PG12)
LTDC_B2: J1.25 U3.AB11(PG10)
LTDC_B3: J1.23 U3.B5(PD10)
LTDC_B4: J1.21 U3.E4(PI4)
LTDC_B5: J1.19 U3.U2(PA3)
LTDC_B6: J1.17 U3.AB10(PB8)
LTDC_B7: J1.15 U3.K3(PD8)
LTDC_CLK: J1.63 U3.AC14(PG7)
LTDC_DE: J1.65 U3.Y12(PF10)
LTDC_G0: J1.45 U3.C6(PE14)
LTDC_G1: J1.43 U3.C10(PE6)
LTDC_G2: J1.41 U3.D1(PH13)
LTDC_G3: J1.39 U3.C3(PH14)
LTDC_G4: J1.37 U3.B1(PH15)
LTDC_G5: J1.35 U3.C1(PI0)
LTDC_G6: J1.33 U3.E3(PI1)
LTDC_G7: J1.31 U3.E2(PI2)
LTDC_HSYNC: J1.67 U3.T1(PI10)
LTDC_R0: J1.61 U3.AB4(PH2)
LTDC_R1: J1.59 U3.AA3(PH3)
LTDC_R2: J1.57 U3.D5(PH8)
LTDC_R3: J1.55 U3.C5(PH9)
LTDC_R4: J1.53 U3.V3(PA5)
LTDC_R5: J1.51 U3.AB5(PC0)
LTDC_R6: J1.49 U3.B2(PH12)
LTDC_R7: J1.47 U3.D3(PE15)
LTDC_VSYNC: J1.69 U3.H4(PI9)
MMC2_CLK: R134.1 U3.C9(PE3)
MMC2_CMD: R133.1 U3.A10(PG6)
MMC2_DAT0: R125.1 U3.C13(PB14)
MMC2_DAT1: R126.1 U3.B12(PB15)
MMC2_DAT2: R127.1 U3.A11(PB3)
MMC2_DAT3: R128.1 U3.B13(PB4)
MMC2_DAT4: R129.1 U3.A13(PA8)
MMC2_DAT5: R130.1 U3.A8(PA9)
MMC2_DAT6: R131.1 U3.C11(PE5)
MMC2_DAT7: R132.1 U3.B11(PC7)
MOC1: J1.68 U3.N2(PA13)
MOC2: J4.43 U3.T2(PA14)
NRST: J4.50 R135.1 R153.1 U3.M3(NRST)
OTG_FS_DM: J2.4 U3.AA18(PA11)
OTG_FS_DP: J2.2 U3.AB19(PA12)
OTG_VBUS: J2.8 U3.AC19(OTG_VBUS)
PA0_WKUP: J4.44 U2.43(INTN) U3.AB3(PA0)
PMIC_WAKEUP: J4.42 U2.2(WAKEUP) U3.K2(PC13)
PONKEYN: J4.46 U2.17(PONKEYN)
PWR_ON: J4.40 R88.1 U2.44(PWRCTRL) U3.R2(PWR_ON)
QSPI_BK1_IO0: J2.12 U3.AC10(PD11)
QSPI_BK1_IO1: J2.14 U3.Y18(PD12)
QSPI_BK1_IO2: J2.16 U3.AB12(PF7)
QSPI_BK1_IO3: J2.18 U3.AA13(PF6)
QSPI_BK2_IO0: J2.20 U3.AA11(PE7)
QSPI_BK2_IO1: J2.22 U3.AC13(PE8)
QSPI_BK2_IO2: J2.24 U3.AA9(PE9)
QSPI_BK2_IO3: J2.26 U3.Y15(PE10)
QSPI_CLK: J2.28 U3.Y16(PB2)
SAI2_FSAm: J2.15 U3.F2(PI7)
SAI2_MCLKA: J2.19 U3.D6(PE0)
SAI2_SCKAm: J2.13 U3.F3(PI5)
SAI2_SDAm: J2.17 U3.F4(PI6)
SAI2_SDBm: J2.21 U3.Y10(PF11)
SDMMC1_CK: J2.37 U3.D13(PC12)
SDMMC1_CMD: J2.35 U3.D12(PD2)
SDMMC1_D0: J2.27 U3.D18(PC8)
SDMMC1_D1: J2.29 U3.D17(PC9)
SDMMC1_D2: J2.31 U3.D15(PC10)
SDMMC1_D3: J2.33 U3.D16(PC11)
SDMMC3_CLK: J2.70 U3.B7(PG15)
SDMMC3_CMD: J2.68 U3.A5(PF1)
SDMMC3_D0: J2.60 U3.D8(PF0)
SDMMC3_D1: J2.62 U3.D9(PF4)
SDMMC3_D2: J2.64 U3.A7(PD5)
SDMMC3_D3: J2.66 U3.D10(PD7)
SPI1_CLK: J2.40 U3.G3(PZ0)
SPI1_MISO: J2.38 U3.G1(PZ1)
SPI1_MOSI: J2.36 U3.J4(PZ2)
SPI5_CLK: J2.46 U3.Y11(PH6)
SPI5_MISO: J2.44 U3.W4(PH7)
SPI5_MOSI: J2.42 U3.AA14(PF9)
STLINK_SWCLK: J4.54 U3.B20(JTCK_SWCLK)
STLINK_SWDIO: J4.52 U3.C20(JTMS_SWDIO)
STUSB1600_IRQOUTn: J2.6 U3.P4(PI11)
TIM4_CH3: J4.36 U3.L3(PD14)
TIM4_CH4: J4.38 U3.J2(PD15)
USART1_CTS: J2.56 U3.G4(PZ3)
USART1_RTS: J2.58 U3.H2(PZ5)
USART1_RX: J2.54 U3.H1(PZ6)
USART1_TX: J2.52 U3.J3(PZ7)
USART2_RX: J2.1 U3.D2(PD6)
USART2_TX: J2.3 U3.D7(PF5)
USB1_N: J4.61 U3.AB17(USB_DM1)
USB1_P: J4.63 U3.AC17(USB_DP1)
USB2_N: J4.67 U3.AB16(USB_DM2)
USB2_P: J4.69 U3.AC16(USB_DP2)
VREF+: C47.1 J4.31 R94.2 U3.R4(VREF+)
VREF_DDR: C27.1 C53.1 C54.1 C201.1 U2.16(VREF) U3.AC20(DDR_VREF) U6.H1(VREF_DQ) U6.M8(VREF_CA)
VTT_DDR: C59.1 C60.1 C61.1 C62.1 C63.1 C64.1 C65.1 C66.1 C67.1 C68.1 C69.1 C70.1 C91.1 C92.1 C93.1 C94.1 C202.1 R17.2 R18.2 R19.2 R20.2 R21.2 R22.2 R23.2 R24.2 R25.2 R26.2 R27.2 R28.2 R29.2 R30.2 R31.2 R32.2 R33.2 R34.2 R35.2 R36.2 R37.2 R38.2 R39.2 R40.2 R119.2 U2.14(LDO3OUT)
N3275089: R13.1 U6.L8(ZQ)
N3282469: R147.1 U8.A6(NC5/VSS)
N3282544: C180.1 U8.C2(VCCI)
N3283232: R125.2 R136.2 U8.A3(DAT0)
N3283236: R126.2 R137.2 U8.A4(DAT1)
N3283240: R127.2 R138.2 U8.A5(DAT2)
N3283244: R128.2 R139.2 U8.B2(DAT3)
N3283248: R129.2 R140.2 U8.B3(DAT4)
N3283252: R130.2 R141.2 U8.B4(DAT5)
N3283256: R131.2 R142.2 U8.B5(DAT6)
N3283260: R132.2 R143.2 U8.B6(DAT7)
N3283264: R133.2 R144.2 U8.M5(CMD)
N3283268: C179.1 R134.2 R145.2 U8.M6(CLK)
N3283272: R135.2 R146.2 U8.K5(~{RST})
N3285898: R148.1 U8.J5(NC60/VSS)
N3300775: L9.1 U2.7(VLX1)
N3300820: C196.1 L9.2 R154.1
N3300941: L10.1 U2.11(VLX2)
N3301067: L11.1 U2.29(VLX3)
N3301183: L12.1 U2.25(VLX4)
N3302965: C208.1 U2.40(INTLDO)
N3306561: R153.2 U2.1(RSTN)
N3308705: L8.2 U2.33(VLXBST)
N3308709: C190.1 L8.1 R149.2
N3309141: R155.1 U2.35(VBUSOTG)
N3309849: R150.2 U2.37(SWIN)
N3309984: R156.1 U2.38(SWOUT)
N3317349: C48.2 U3.AB15(VDDA1V1_REG)
N3317353: C49.1 C50.1 R95.2 U3.AB14(VDDA1V8_REG) U3.C14(VDDA1V8_DSI)
N3322011: C51.1 C142.1 U3.C17(VDD1V2_DSI_PHY) U3.C18(VDD1V2_DSI_REG)
N3340590: C46.1 L5.2 R93.2 R94.1 U3.1H1(VDDA)
N3340594: L5.1 R12.2
N3362916: R10.1 U3.K23(DDR_ZQ)
N3364394: TP102.1(TP) U3.Y19(DDR_ATO)
N3364398: TP103.1(TP) U3.K20(DDR_DTO0)
N3364402: TP104.1(TP) U3.L21(DDR_DTO1)
N3371131: C108.1 OSC1.3(CLK) R4.1
N3371139: C106.2 OSC1.4(VDD) R87.2
N3371143: C107.2 OSC1.1(EN) R1.2 R88.2 R90.1
N3374325: R81.1 R82.1 U3.AB13(BYPASS_REG1V8)
N3375018: R83.1 R85.2 U3.R3(PDR_ON)
N3375025: R84.1 R86.2 U3.T3(PDR_ON_CORE)
N3375486: C105.1 U3.M4(NRST_CORE)
N3376367: R80.1 U3.AB18(USB_RREF)
N3444553: C109.1 R2.2 X1.1
N3444560: C110.1 R79.1 X1.2
N3457313: TP101.1(TP) U3.N3(PWR_LP)
N3836449: LED2.1(A) R5.2
N3836598: LED1.1(A) R6.2 R7.2

Not connected (* = marked no-connect by the designer): J4 29* 30*; U3 A21(DDR_DQ20)* A22(DDR_DQ23)* AA20(DDR_DQM3)* AA22(DDR_DQ31)* AA23(DDR_DQ30)* AB20(DDR_DQ27)* AB21(DDR_DQ26)* AB22(DDR_DQS3P)* AB23(DDR_DQS3N)* AC21(DDR_DQ29)* AC22(DDR_DQ28)* B21(DDR_DQ19)* B22(DDR_DQ16)* B23(DDR_DQS2N)* C22(DDR_DQS2P)* C23(DDR_DQM2)* D21(DDR_DQ22)* D22(DDR_DQ17)* D23(DDR_DQ18)* E23(DDR_DQ21)* Y22(DDR_DQ25)* Y23(DDR_DQ24)*; U6 J1(NC1)* J9(NC2)* L1(NC3)* L9(NC4)*; U8 A1(NC11)* A2(NC4)* A7(NC6)* A8(NC7)* A9(NC18)* A10(NC95)* A11(NC94)* A12(NC93)* A13(NC92)* A14(NC91)* B1(NC90)* B7(NC89)* B8(NC74)* B9(NC53)* B10(NC52)* B11(NC51)* B12(NC50)* B13(NC49)* B14(NC19)* C1(NC34)* C3(NC33)* C5(NC32)* C7(NC31)* C8(NC30)* C9(NC29)* C10(NC25)* C11(NC23)* C12(NC22)* C13(NC21)* C14(NC20)* D1(NC48)* D2(NC46)* D3(NC39)* D4(NC38)* D12(NC37)* D13(NC36)* D14(NC35)* E1(NC1)* E2(NC2)* E3(NC3)* E5(NC121)* E8(NC8)* E9(NC9)* E10(NC10)* E12(NC12)* E13(NC13)* E14(NC14)* F1(NC15)* F2(NC16)* F3(NC17)* F10(NC24)* F12(NC26)* F13(NC27)* F14(NC28)* G1(NC88)* G2(NC81)* G3(NC79)* G10(NC78)* G12(NC40)* G13(NC41)* G14(NC42)* H1(NC43)* H2(NC44)* H3(NC45)* H5(NC47/DS)* H12(NC54)* H13(NC55)* H14(NC56)* J1(NC57)* J2(NC58)* J3(NC59)* J12(NC117)* J13(NC69)* J14(NC70)* K1(NC71)* K2(NC72)* K3(NC73)* K6(NC123)* K7(NC77)* K10(NC80)* K12(NC82)* K13(NC83)* K14(NC84)* L1(NC85)* L2(NC86)* L3(NC87)* L12(NC96)* L13(NC97)* L14(NC98)* M1(NC99)* M2(NC100)* M3(NC101)* M7(NC105)* M8(NC106)* M9(NC107)* M10(NC108)* M11(NC109)* M12(NC110)* M13(NC111)* M14(NC112)* N1(NC113)* N3(NC115)* N6(NC122)* N7(NC118)* N8(NC119)* N9(NC120)* N10(NC75)* N11(NC76)* N12(NC68)* N13(NC67)* N14(NC66)* P1(NC65)* P2(NC64)* P7(NC63)* P8(NC61)* P9(NC62)* P10(NC114)* P11(NC104)* P12(NC103)* P13(NC102)* P14(NC116)*

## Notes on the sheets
sheet 1
- UART4_TX
- UART4_RX
sheet 3
- DDR3L SDRAM
- 4Gb DDR3
sheet 4
- Layout Note:
- Place R134 C179 Close To MPU.
- eMMC
- 4GB
sheet 5
- Defaut Output:1.2V
- Layout Note:
- Layout Note:
- 5V_VIN  3A
- VDD_CORE      1~1.5A
- VDDQ_DDR      1A
- VDD          500mA
- Defaut Output:1.1V
- 3V3         2A
- BST_OUT      1A
- VBUS_OTG     500mA
- VBUS_SW       1A
- VREF_DDR     100mA
- VTT_DDR    200mA
- Defaut Output:3.3V
- 1V8_AUDIO     350mA
- 1V2_HDMI       200mA
- 3V3_HDMI       350mA
- VDDA          350mA
- VDD_USB   100mA
- Defaut Output:3.3V
- Defaut Output:5.2V
- Layout Note:
- BST_OUT  1A
- Defaut Output:VOUT2/2
- Defaut Output:0.675V
- Defaut Output:1.8V
- Defaut Output:1.2V
- Defaut Output:3.3V
- Defaut Output:2.9V
- Defaut Output:3.3V
sheet 6
- Layout Note:
- The RGMII signals must be length-matched
- Half-Duplex Master
- by RX,TX and MDC groups
- Layout Note:
- Differential impedance:90 Ohm
- QSPI_BK1_NCS
- OTG_FS_ID
- I2C4_SCL
- SPI5_NSS
- DVP_D12
- SAI2_SDBm
- Layout Note:
- The SDMMC1 signals must be length-matched
- UART4_RX
- I2S2_SDI
- DVP_D8
- DVP_D11
- FDCAN1_RX
- FDCAN1_TX
- DVP_D10
- Layout Note:
- Differential impedance:100 Ohm
- DVP_D9
- I2C4_SDA
- DAC1_OUT2
- QSPI_BK2_NCS
- WiFi/BLE Interface
- DVP_D13
- QSPI_CLK
- SPI1_NSS
- Layout Note:
- The LTCD signals must be length-matched
- Layout Note:
- The DCMI signals must be length-matched
- Layout Note:
- The SDMMC3 signals must be length-matched
- Power LED
- Layout Note:
- Wire according to the differential signal
- State LED
- SPI5_MISO
- UART4_TX
- GPIO_PG3
- I2C6_SDA
- I2C6_SCL
- Layout Note:
- Differential impedance:90 Ohm
sheet 7
- Schematic: Seeed SoM - STM32MP157C
- Revision History
- SHEET
- SHEET NAME
- DATE
- REVISION
- DESCRIPTION
- 01
- Title/Revision History
- 2019/05/21
- Seeed SoM - STM32MP157C_v1.0_SCH_190521
- Initial Release
- 02
- MPU_1
- 2019/09/04
- Seeed SoM - STM32MP157C_v1.01_SCH_190904
- 03
- MPU_2
- 2019/12/13
- Seeed SoM - STM32MP157C_v1.01_SCH_191213
- Change R5,R6 from 1k to 2k
- 04
- DDR3
- 05
- eMMC
- 06
- PMU
- 07
- PINOUT/LED
